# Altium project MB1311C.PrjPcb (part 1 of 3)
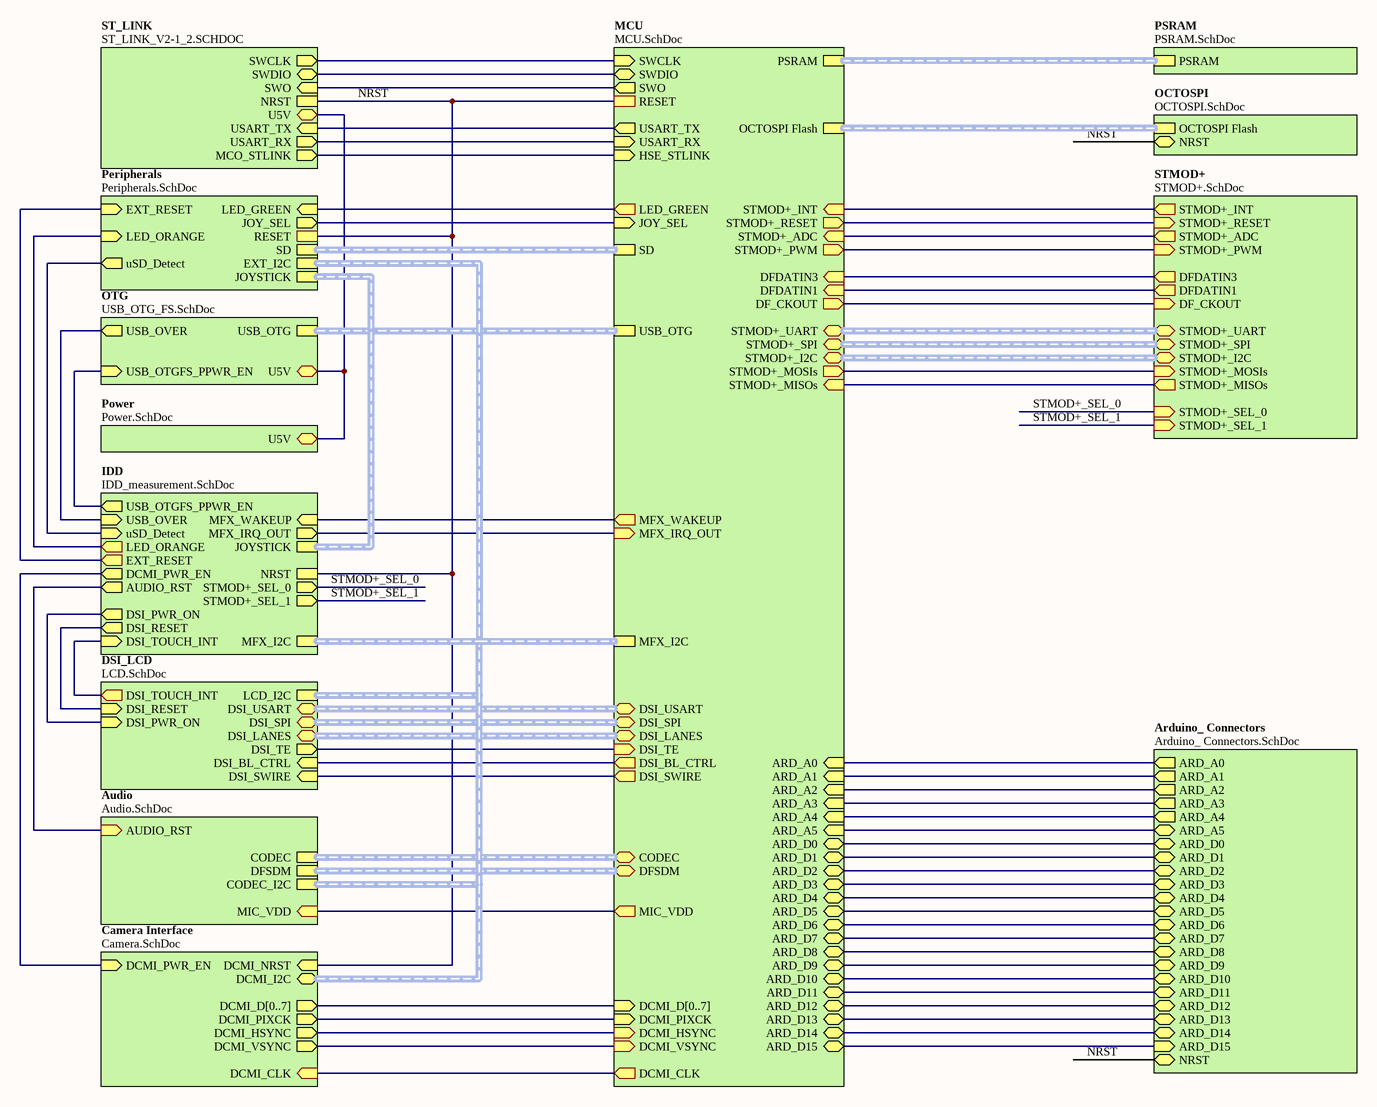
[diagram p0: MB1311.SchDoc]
14 sheets, 364 parts. Net scope: hierarchical (ports join the sheet entries above them; power ports are global).
Board file: MB1311C.PcbDoc
Sheets:
  MB1311.SchDoc
    Arduino_ Connectors = Arduino_ Connectors.SchDoc
    Camera Interface = Camera.SchDoc
    IDD = IDD_measurement.SchDoc
    DSI_LCD = LCD.SchDoc
    MCU = MCU.SchDoc
    Peripherals = Peripherals.SchDoc
    Power = Power.SchDoc
    PSRAM = PSRAM.SchDoc
    OCTOSPI = OCTOSPI.SchDoc
    ST_LINK = ST_LINK_V2-1_2.SCHDOC
    OTG = USB_OTG_FS.SchDoc
    STMOD+ = STMOD+.SchDoc
    Audio = Audio.SchDoc

## Sheet MB1311.SchDoc: MB1311-TOP
size A3; Date: 18/07/2017; Author: P.A.; CompanyName: STMicroelectronics; Organization: Microcontrollers Division; Address1: 12, Rue Jules HOROWITZ; Address2: 38019 Grenoble; Address3: FRANCE; DocumentNumber: MB1311; Revision: C; SheetNumber: 1; SheetTotal: 14; Project: STM32L4R9I-DISCO; PageSetup: Record=PageOptions¦CenterHorizontal=True¦CenterVertical=True¦PrintScale=1.00¦XCorrection=1.00¦YCorrection=1.00¦PrintKind=1¦BorderSize=5000000¦LeftOffset=0¦BottomOffset=0¦Orientation=2¦PaperLength=1000¦PaperWidth=1000¦Scale=100¦PaperSource=7¦PrintQuality=-3¦MediaType=1¦DitherType=10¦PrintScaleMode=1¦PaperKind=Letter¦PaperIndex=1

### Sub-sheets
Arduino_ Connectors = Arduino_ Connectors.SchDoc: NRST (bidir), ARD_A0 (out), ARD_A1 (out), ARD_A2 (out), ARD_A3 (out), ARD_A4 (out), ARD_A5 (bidir), ARD_D5 (bidir), ARD_D4 (bidir), ARD_D3 (bidir), ARD_D2 (bidir), ARD_D1 (bidir), ARD_D0 (bidir), ARD_D13 (bidir), ARD_D12 (bidir), ARD_D11 (bidir), ARD_D10 (bidir), ARD_D9 (bidir), ARD_D8 (bidir), ARD_D6 (bidir), ARD_D7 (bidir), ARD_D15 (in), ARD_D14 (bidir)
Audio = Audio.SchDoc: CODEC (harness SAI), CODEC_I2C (harness I2C), DFSDM (harness DFSDM), MIC_VDD (in), AUDIO_RST (in)
Camera Interface = Camera.SchDoc: DCMI_D[0..7] (out), DCMI_NRST (in), DCMI_PWR_EN (in), DCMI_VSYNC (out), DCMI_HSYNC (out), DCMI_PIXCK (out), DCMI_I2C (harness I2C), DCMI_CLK (in)
DSI_LCD = LCD.SchDoc: LCD_I2C (harness I2C), DSI_RESET (in), DSI_TOUCH_INT (out), DSI_USART (harness DSI_USART), DSI_SPI (harness DSI_SPI), DSI_BL_CTRL (in), DSI_PWR_ON (in), DSI_SWIRE (in), DSI_TE (out), DSI_LANES (harness DSI_LANES)
IDD = IDD_measurement.SchDoc: MFX_IRQ_OUT (out), MFX_WAKEUP (in), NRST, MFX_I2C (harness I2C), USB_OTGFS_PPWR_EN (out), DCMI_PWR_EN (out), uSD_Detect (in), USB_OVER (in), DSI_RESET (out), LED_ORANGE (out), DSI_TOUCH_INT (in), AUDIO_RST (out), EXT_RESET (out), DSI_PWR_ON (out), JOYSTICK (harness JOYSTICK), STMOD+_SEL_0 (out), STMOD+_SEL_1 (out)
MCU = MCU.SchDoc: OCTOSPI Flash (harness OCTOSPI), PSRAM (harness PSRAM), SD (harness SD), USB_OTG (harness USB_OTG), MFX_IRQ_OUT (in), MFX_WAKEUP (out), ARD_A0 (in), MFX_I2C (harness I2C), ARD_A1 (in), ARD_A2 (in), ARD_A3 (in), ARD_A4 (in), ARD_A5 (in), ARD_D0 (bidir), ARD_D1 (bidir), ARD_D2 (bidir), ARD_D3 (bidir), ARD_D4 (bidir), ARD_D5 (bidir), ARD_D6 (bidir), ARD_D7 (bidir), ARD_D8 (bidir), ARD_D9 (bidir), ARD_D10 (bidir), ARD_D11 (bidir), ARD_D12 (bidir), ARD_D13 (bidir), ARD_D14 (bidir), ARD_D15 (bidir), USART_TX (out), USART_RX (in), SWCLK (in), SWDIO (bidir), SWO (out), DCMI_D[0..7] (in), DCMI_VSYNC (in), DCMI_HSYNC (in), DCMI_PIXCK (in), STMOD+_UART (harness UART), STMOD+_I2C (harness I2C), STMOD+_INT (in), STMOD+_RESET (out), STMOD+_ADC (in), STMOD+_PWM (out), STMOD+_MOSIs (out), STMOD+_MISOs (in), STMOD+_SPI (harness SPI), DFDATIN3 (in), DFDATIN1 (in), DFSDM (harness DFSDM), MIC_VDD (out), CODEC (harness SAI), LED_GREEN (out), RESET, DCMI_CLK (out), DF_CKOUT (out), DSI_USART (harness DSI_USART), DSI_SPI (harness DSI_SPI), JOY_SEL (in), DSI_TE (in), DSI_LANES (harness DSI_LANES), DSI_BL_CTRL (out), DSI_SWIRE (out), HSE_STLINK (in)
OCTOSPI = OCTOSPI.SchDoc: OCTOSPI Flash (harness OCTOSPI), NRST (bidir)
OTG = USB_OTG_FS.SchDoc: USB_OTG (harness USB_OTG), USB_OTGFS_PPWR_EN (in), USB_OVER (out), U5V
Peripherals = Peripherals.SchDoc: LED_GREEN (in), SD (harness SD), JOYSTICK (harness JOYSTICK), LED_ORANGE (in), uSD_Detect (out), RESET, JOY_SEL (out), EXT_RESET (in), EXT_I2C (harness I2C)
Power = Power.SchDoc: U5V
PSRAM = PSRAM.SchDoc: PSRAM (harness PSRAM)
ST_LINK = ST_LINK_V2-1_2.SCHDOC: NRST, SWCLK (out), SWDIO (bidir), SWO (in), USART_TX (in), USART_RX (out), U5V, MCO_STLINK (out)
STMOD+ = STMOD+.SchDoc: STMOD+_INT (out), STMOD+_RESET (in), STMOD+_ADC (out), DFDATIN3 (out), STMOD+_PWM (in), DFDATIN1 (out), STMOD+_UART (harness UART), STMOD+_SPI (harness SPI), STMOD+_I2C (harness I2C), STMOD+_MOSIs (in), STMOD+_MISOs (out), DF_CKOUT (in), STMOD+_SEL_1 (in), STMOD+_SEL_0 (in)

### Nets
ARD_A0: sheet Arduino_ Connectors/ARD_A0, sheet MCU/ARD_A0
ARD_A1: sheet Arduino_ Connectors/ARD_A1, sheet MCU/ARD_A1
ARD_A2: sheet Arduino_ Connectors/ARD_A2, sheet MCU/ARD_A2
ARD_A3: sheet Arduino_ Connectors/ARD_A3, sheet MCU/ARD_A3
ARD_A4: sheet Arduino_ Connectors/ARD_A4, sheet MCU/ARD_A4
ARD_A5: sheet Arduino_ Connectors/ARD_A5, sheet MCU/ARD_A5, sheet MCU/STMOD+_PWM, sheet STMOD+/STMOD+_PWM
ARD_D0: sheet Arduino_ Connectors/ARD_D0, sheet MCU/ARD_D0
ARD_D1: sheet Arduino_ Connectors/ARD_D1, sheet MCU/ARD_D1
ARD_D2: sheet Arduino_ Connectors/ARD_D2, sheet MCU/ARD_D2
ARD_D3: sheet Arduino_ Connectors/ARD_D3, sheet MCU/ARD_D3
ARD_D4: sheet Arduino_ Connectors/ARD_D4, sheet MCU/ARD_D4
ARD_D5: sheet Arduino_ Connectors/ARD_D5, sheet MCU/ARD_D5
ARD_D6: sheet Arduino_ Connectors/ARD_D6, sheet MCU/ARD_D6
ARD_D7: sheet Arduino_ Connectors/ARD_D7, sheet Camera Interface/DCMI_HSYNC, sheet MCU/ARD_D7, sheet MCU/DCMI_HSYNC, sheet MCU/STMOD+_ADC, sheet STMOD+/STMOD+_ADC
ARD_D8: sheet Arduino_ Connectors/ARD_D8, sheet MCU/ARD_D8
ARD_D9: sheet Arduino_ Connectors/ARD_D9, sheet MCU/ARD_D9
ARD_D10: sheet Arduino_ Connectors/ARD_D10, sheet MCU/ARD_D10
ARD_D11: sheet Arduino_ Connectors/ARD_D11, sheet MCU/ARD_D11
ARD_D12: sheet Arduino_ Connectors/ARD_D12, sheet MCU/ARD_D12
ARD_D13: sheet Arduino_ Connectors/ARD_D13, sheet MCU/ARD_D13
ARD_D14: sheet Arduino_ Connectors/ARD_D14, sheet MCU/ARD_D14
ARD_D15: sheet Arduino_ Connectors/ARD_D15, sheet MCU/ARD_D15
CKOUT: sheet MCU/DF_CKOUT, sheet STMOD+/DF_CKOUT
DATIN1: sheet MCU/DFDATIN1, sheet STMOD+/DFDATIN1
DCMI_CLK: sheet Camera Interface/DCMI_CLK, sheet DSI_LCD/DSI_SWIRE, sheet MCU/DCMI_CLK, sheet MCU/DSI_SWIRE
DCMI_D0: sheet MCU/STMOD+_INT, sheet STMOD+/STMOD+_INT
DCMI_D1: sheet MCU/DFDATIN3, sheet STMOD+/DFDATIN3
DCMI_D7: sheet MCU/STMOD+_RESET, sheet STMOD+/STMOD+_RESET
DCMI_PIXCLK: sheet Camera Interface/DCMI_PIXCK, sheet MCU/DCMI_PIXCK
DCMI_PWR_EN: sheet Camera Interface/DCMI_PWR_EN, sheet IDD/DCMI_PWR_EN
DCMI_VSYNC: sheet Camera Interface/DCMI_VSYNC, sheet MCU/DCMI_VSYNC
DSI_BL_CTRL: sheet DSI_LCD/DSI_BL_CTRL, sheet MCU/DSI_BL_CTRL
DSI_PWR_ON: sheet IDD/DSI_PWR_ON, sheet DSI_LCD/DSI_PWR_ON
DSI_TE: sheet DSI_LCD/DSI_TE, sheet MCU/DSI_TE
JOY_SEL: sheet MCU/JOY_SEL, sheet Peripherals/JOY_SEL
LED_GREEN: sheet MCU/LED_GREEN, sheet Peripherals/LED_GREEN
MCO: sheet MCU/HSE_STLINK, sheet ST_LINK/MCO_STLINK
MFX_IRQ_OUT: sheet IDD/MFX_IRQ_OUT, sheet MCU/MFX_IRQ_OUT
MFX_WAKEUP: sheet IDD/MFX_WAKEUP, sheet MCU/MFX_WAKEUP
MIC_VDD: sheet MCU/MIC_VDD, sheet Audio/MIC_VDD
NRST: sheet Arduino_ Connectors/NRST, sheet Camera Interface/DCMI_NRST, sheet IDD/NRST, sheet MCU/RESET, sheet Peripherals/RESET, sheet OCTOSPI/NRST, sheet ST_LINK/NRST  [project net DCMI_NRST]
SPI2_MISOs: sheet MCU/STMOD+_MISOs, sheet STMOD+/STMOD+_MISOs
SPI2_MOSIs: sheet MCU/STMOD+_MOSIs, sheet STMOD+/STMOD+_MOSIs
STMOD+_SEL_0: sheet IDD/STMOD+_SEL_0, sheet STMOD+/STMOD+_SEL_0  [project net PMOD_SEL_0]
STMOD+_SEL_1: sheet IDD/STMOD+_SEL_1, sheet STMOD+/STMOD+_SEL_1  [project net PMOD_SEL_1]
SWCLK: sheet MCU/SWCLK, sheet ST_LINK/SWCLK
SWDIO: sheet MCU/SWDIO, sheet ST_LINK/SWDIO
SWO: sheet MCU/SWO, sheet ST_LINK/SWO
TOUCH_INT: sheet IDD/DSI_TOUCH_INT, sheet DSI_LCD/DSI_TOUCH_INT
USART2_RX: sheet MCU/USART_RX, sheet ST_LINK/USART_RX
USART2_TX: sheet MCU/USART_TX, sheet ST_LINK/USART_TX
USB_OTGFS_OVRCR: sheet IDD/USB_OVER, sheet OTG/USB_OVER
USB_OTGFS_VBUS: sheet Power/U5V, sheet ST_LINK/U5V, sheet OTG/U5V
uSD_Detect: sheet IDD/uSD_Detect, sheet Peripherals/uSD_Detect
NetCN4_57: sheet IDD/DSI_RESET, sheet DSI_LCD/DSI_RESET
NetR3_1: sheet IDD/LED_ORANGE, sheet Peripherals/LED_ORANGE
NetR41_2: sheet IDD/USB_OTGFS_PPWR_EN, sheet OTG/USB_OTGFS_PPWR_EN
NetR83_2: sheet IDD/AUDIO_RST, sheet Audio/AUDIO_RST
NetR112_2: sheet IDD/EXT_RESET, sheet Peripherals/EXT_RESET

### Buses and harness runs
bus sheet Camera Interface/DCMI_D[0..7] = sheet MCU/DCMI_D[0..7]
harness sheet Audio/CODEC = sheet MCU/CODEC
harness sheet Audio/CODEC_I2C = sheet Camera Interface/DCMI_I2C = sheet DSI_LCD/LCD_I2C = sheet IDD/MFX_I2C = sheet MCU/MFX_I2C = sheet Peripherals/EXT_I2C
harness sheet Audio/DFSDM = sheet MCU/DFSDM
harness sheet DSI_LCD/DSI_LANES = sheet MCU/DSI_LANES
harness sheet DSI_LCD/DSI_SPI = sheet MCU/DSI_SPI
harness sheet DSI_LCD/DSI_USART = sheet MCU/DSI_USART
harness sheet IDD/JOYSTICK = sheet Peripherals/JOYSTICK
harness sheet MCU/OCTOSPI Flash = sheet OCTOSPI/OCTOSPI Flash
harness sheet MCU/PSRAM = sheet PSRAM/PSRAM
harness sheet MCU/SD = sheet Peripherals/SD
harness sheet MCU/STMOD+_I2C = sheet STMOD+/STMOD+_I2C
harness sheet MCU/STMOD+_SPI = sheet STMOD+/STMOD+_SPI
harness sheet MCU/STMOD+_UART = sheet STMOD+/STMOD+_UART
harness sheet MCU/USB_OTG = sheet OTG/USB_OTG

## Sheet Arduino_ Connectors.SchDoc: Arduino Uno connector
size A4; Author: P.A.; CompanyName: STMicroelectronics; Organization: Microcontrollers Division; Address1: 12, Rue Jules HOROWITZ; Address2: 38019 Grenoble; Address3: FRANCE; DocumentNumber: MB1311; Revision: C; SheetNumber: 3; SheetTotal: 14; Project: STM32L4R9I-DISCO
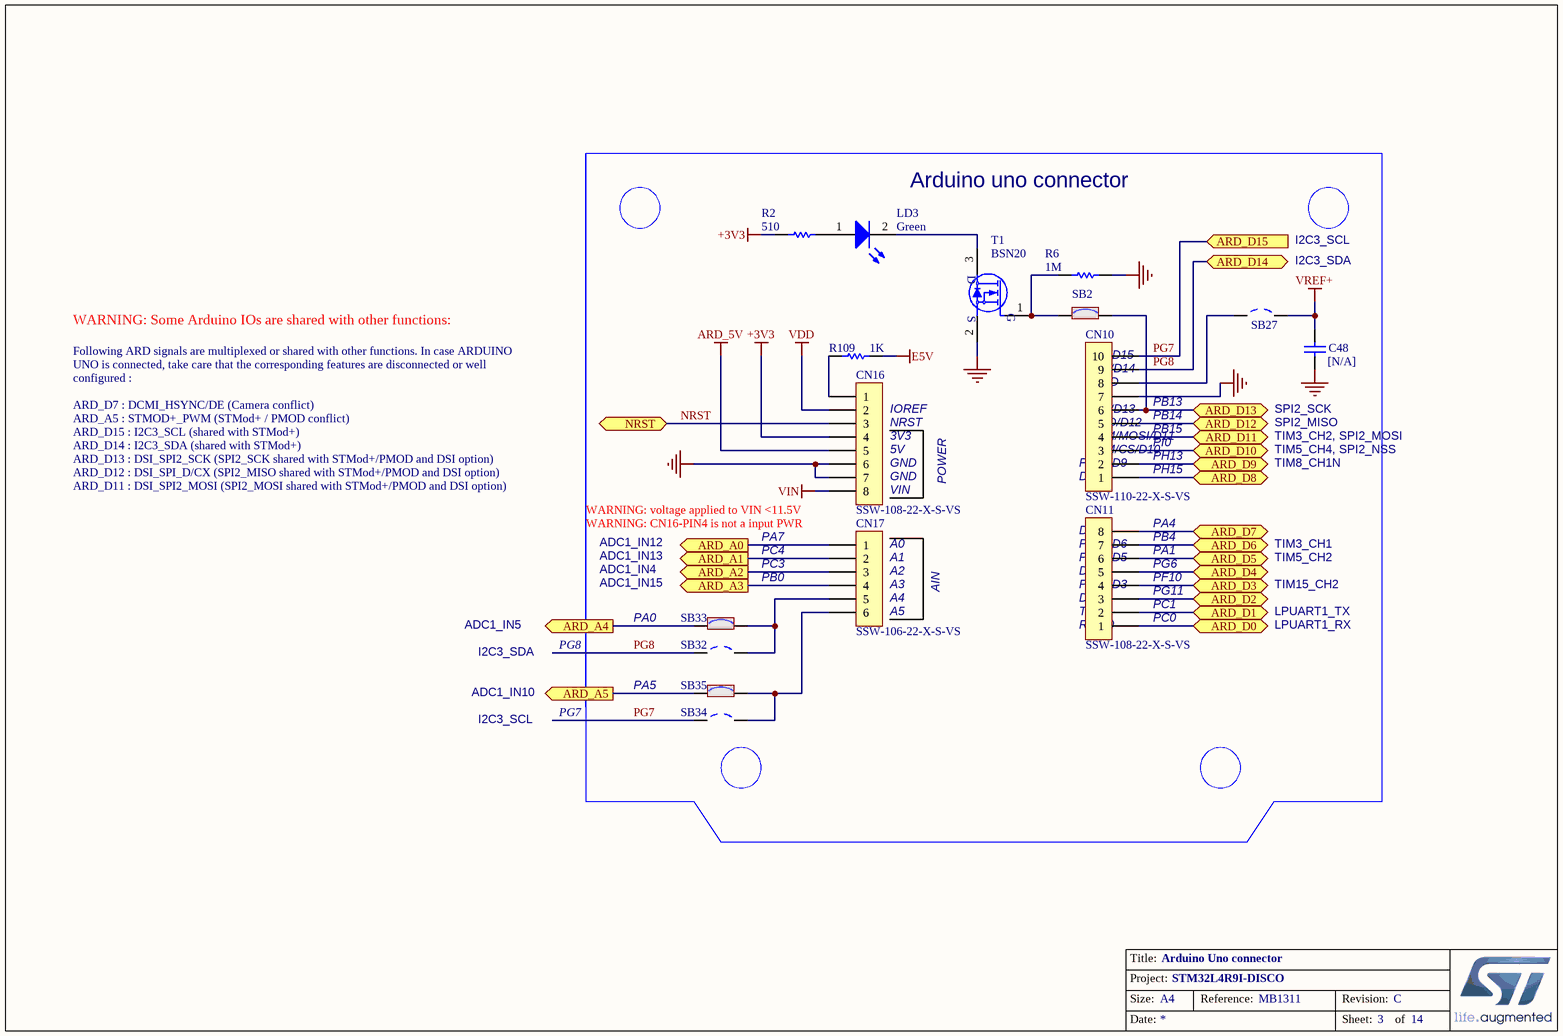
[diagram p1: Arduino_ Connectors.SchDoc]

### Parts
C48  [N/A]  [C0603]
CN10  SSW-110-22-X-S-VS  [CON_SAMTEC_SSW-110-22-X-S-VS]
CN11  SSW-108-22-X-S-VS  [CON_SAMTEC_SSW-108-22-X-S-VS]
CN16  SSW-108-22-X-S-VS  [CON_SAMTEC_SSW-108-22-X-S-VS]
CN17  SSW-106-22-X-S-VS  [CON_SAMTEC_SSW-106-22-X-S-VS]
LD3  Corlor: Green  [LED_0603_GREEN_H0P8]  (hidden comment: 19-213SY6C/S530-E2/TR8LED)
R2  value 510  [R0603]  (hidden comment: RC0603JR-07510RL)
R6  1M  [R0603]
R109  1K  [R0603]
SB2  Solder Bridge ON  [SOLDER-BRIDGE_R0603-0R]  (value not drawn)
SB27  Solder Bridge OFF  [SOLDER-BRIDGE_R0603-0R]  (value not drawn)
SB32  Solder Bridge OFF  [SOLDER-BRIDGE_R0603-0R]  (value not drawn)
SB33  Solder Bridge ON  [SOLDER-BRIDGE_R0603-0R]  (value not drawn)
SB34  Solder Bridge OFF  [SOLDER-BRIDGE_R0603-0R]  (value not drawn)
SB35  Solder Bridge ON  [SOLDER-BRIDGE_R0603-0R]  (value not drawn)
T1  BSN20  [MOS_SOT23]

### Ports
ARD_A0 (out), ARD_A1 (out), ARD_A2 (out), ARD_A3 (out), ARD_A4 (out), ARD_A5 (out), ARD_D0 (bidir), ARD_D1 (bidir), ARD_D2 (bidir), ARD_D3 (bidir), ARD_D4 (bidir), ARD_D5 (bidir), ARD_D6 (bidir), ARD_D7 (bidir), ARD_D8 (bidir), ARD_D9 (bidir), ARD_D10 (bidir), ARD_D11 (bidir), ARD_D12 (bidir), ARD_D13 (bidir), ARD_D14 (bidir), ARD_D15 (in), NRST (bidir)

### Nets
+3V3: CN16.4 R2.1
ARD_5V: CN16.5
E5V: R109.1
GND: C48.2 CN10.7 CN16.6 CN16.7 R6.2 T1.2(S)
VDD: CN16.2
VIN: CN16.8
VREF+: C48.1 SB27.2
ARD_A0: CN17.1 ; port ARD_A0
ARD_A1: CN17.2 ; port ARD_A1
ARD_A2: CN17.3 ; port ARD_A2
ARD_A3: CN17.4 ; port ARD_A3
ARD_A4: SB33.1 ; port ARD_A4
ARD_A5: SB35.1 ; port ARD_A5
ARD_D0: CN11.1 ; port ARD_D0
ARD_D1: CN11.2 ; port ARD_D1
ARD_D2: CN11.3 ; port ARD_D2
ARD_D3: CN11.4 ; port ARD_D3
ARD_D4: CN11.5 ; port ARD_D4
ARD_D5: CN11.6 ; port ARD_D5
ARD_D6: CN11.7 ; port ARD_D6
ARD_D7: CN11.8 ; port ARD_D7
ARD_D8: CN10.1 ; port ARD_D8
ARD_D9: CN10.2 ; port ARD_D9
ARD_D10: CN10.3 ; port ARD_D10
ARD_D11: CN10.4 ; port ARD_D11
ARD_D12: CN10.5 ; port ARD_D12
ARD_D13: CN10.6 SB2.2 ; port ARD_D13
NRST: CN16.3 ; port NRST  [project net DCMI_NRST]
PG7: CN10.10 SB34.1 ; port ARD_D15  [project net ARD_D15]
PG8: CN10.9 SB32.1 ; port ARD_D14  [project net ARD_D14]
NetCN10_8: CN10.8 SB27.1
NetCN16_1: CN16.1 R109.2
NetCN17_5: CN17.5 SB32.2 SB33.2
NetCN17_6: CN17.6 SB34.2 SB35.2
NetLD3_1: LD3.1(A) R2.2
NetLD3_2: LD3.2(K) T1.3(D)
NetR6_1: R6.1 SB2.1 T1.1(G)

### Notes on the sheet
- Arduino uno connector
- I2C3_SCL
- I2C3_SDA
- WARNING: Some Arduino IOs are shared with other functions:
- (near CN10) SDA/D14
- SCL/D15
- (near CN10) AVDD
- IOREF
- (near CN16) NRST
- (near CN16) 3V3
- (near CN10) SCK/D13
- (near CN10) MISO/D12
- (near CN10) PWM/MOSI/D11
- (near CN10) GND
- (near CN10) PI0
- (near CN10) PB15
- (near CN10) PB14
- (near CN10) PB13
- TIM3_CH2, SPI2_MOSI
- SPI2_MISO
- (near C48) SPI2_SCK
- Following ARD signals are multiplexed or shared with other functions. In case ARDUINO UNO is connected, take care that the corresponding features are disconnected or well configured :
  ARD_D7 : DCMI_HSYNC/DE (Camera conflict)
  ARD_A5 : STMOD+_PWM (STMod+ / PMOD conflict)
  ARD_D15 : I2C3_SCL (shared with STMod+)
  ARD_D14 : I2C3_SDA (shared with STMod+)
  ARD_D13 : DSI_SPI2_SCK (SPI2_SCK shared with STMod+/PMOD and DSI option)
  ARD_D12 : DSI_SPI_D/CX (SPI2_MISO shared with STMod+/PMOD and DSI option)
  ARD_D11 : DSI_SPI2_MOSI (SPI2_MOSI shared with STMod+/PMOD and DSI option)
- WARNING: voltage applied to VIN <11.5V
- (near CN16) 5V
- (near CN16) GND
- (near CN16) VIN
- POWER
- (near CN10) D8
- (near CN10) PWM/D9
- (near CN10) PWM/CS/D10
- (near CN10) PH15
- (near CN10) PH13
- TIM8_CH1N
- TIM5_CH4, SPI2_NSS
- WARNING: CN16-PIN4 is not a input PWR
- ADC1_IN4
- ADC1_IN13
- ADC1_IN12
- ADC1_IN15
- PA7
- PC4
- PC3
- PB0
- (near CN17) A0
- (near CN17) A1
- (near CN17) A2
- (near CN11) D4
- (near CN11) PWM/D5
- (near CN11) PWM/D6
- (near CN11) D7
- (near CN11) PG6
- (near CN11) PA1
- (near CN11) PB4
- PA4
- (near CN11) PF10
- TIM5_CH2
- TIM3_CH1
- ADC1_IN5
- PG8
- PA0
- (near CN17) A3
- (near CN17) A4
- (near CN17) A5
- AIN
- (near CN11) RX/D0
- (near CN11) TX/D1
- (near CN11) D2
- (near CN11) PWM/D3
- (near CN11) PC1
- (near CN11) PC0
- (near CN11) PG11
- LPUART1_TX
- LPUART1_RX
- TIM15_CH2
- ADC1_IN10
- PG7
- PA5

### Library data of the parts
C48 = Cap: Capacitor,100nF,10%,16V,X7R,0603,YAGEO; Manuf_Part_1: CC0603KRX7R7BB104; Ordered by: Subcon
CN10 = Header 10X1_Female: Header, 10-Pin, Single row,female; Manuf_1: SAMTEC; Ordered by: Subcon; ECCN_US/EU: NA
CN11 CN16 = Header 8X1_Female: Header, 8-Pin, Single row,female; Manuf_1: SAMTEC; Ordered by: Subcon; ECCN_US/EU: NA
CN17 = Header 6X1_Female: Header, 6-Pin, Single row,female; Manuf_1: SAMTEC; Ordered by: Subcon; ECCN_US/EU: NA
LD3 = LED2: LED,Green,0603; Manuf_1: Everlight; Ordered by: Subcon; ECCN_US/EU: EAR99/NEC
R2 = res1: Resistor, 510R , 0603,1%,YAGEO; Ordered by: Subcon; ECCN_US/EU: NA
R6 = res1: Resistor, 1M , 0603; Ordered by: Subcon; ECCN_US/EU: NA
R109 = res1: Resistor,1K,0603,1%; Manuf_1: YAGEO; Manuf_Part_1: RC0603FR-071KL; Ordered by: Subcon; ECCN_US/EU: NA
SB2 SB33 SB35 = SB_ON: Manuf_1: YAGEO; Manuf_Part_1: RC0603JR-070RL; Solder: YES; Ordered By: Subcon
SB27 SB32 SB34 = SB_OFF: Solder: NO
T1 = 2N7000: Manuf_1: DIODES; Manuf_Part_1: BSN20-7; Ordered by: Subcon

## Sheet Camera.SchDoc: Camera
size A4; Author: P.A.; CompanyName: STMicroelectronics; Organization: Microcontrollers Division; Address1: 12, Rue Jules HOROWITZ; Address2: 38019 Grenoble; Address3: FRANCE; DocumentNumber: MB1311; Revision: C; SheetNumber: 12; SheetTotal: 14; Project: STM32L4R9I-DISCO
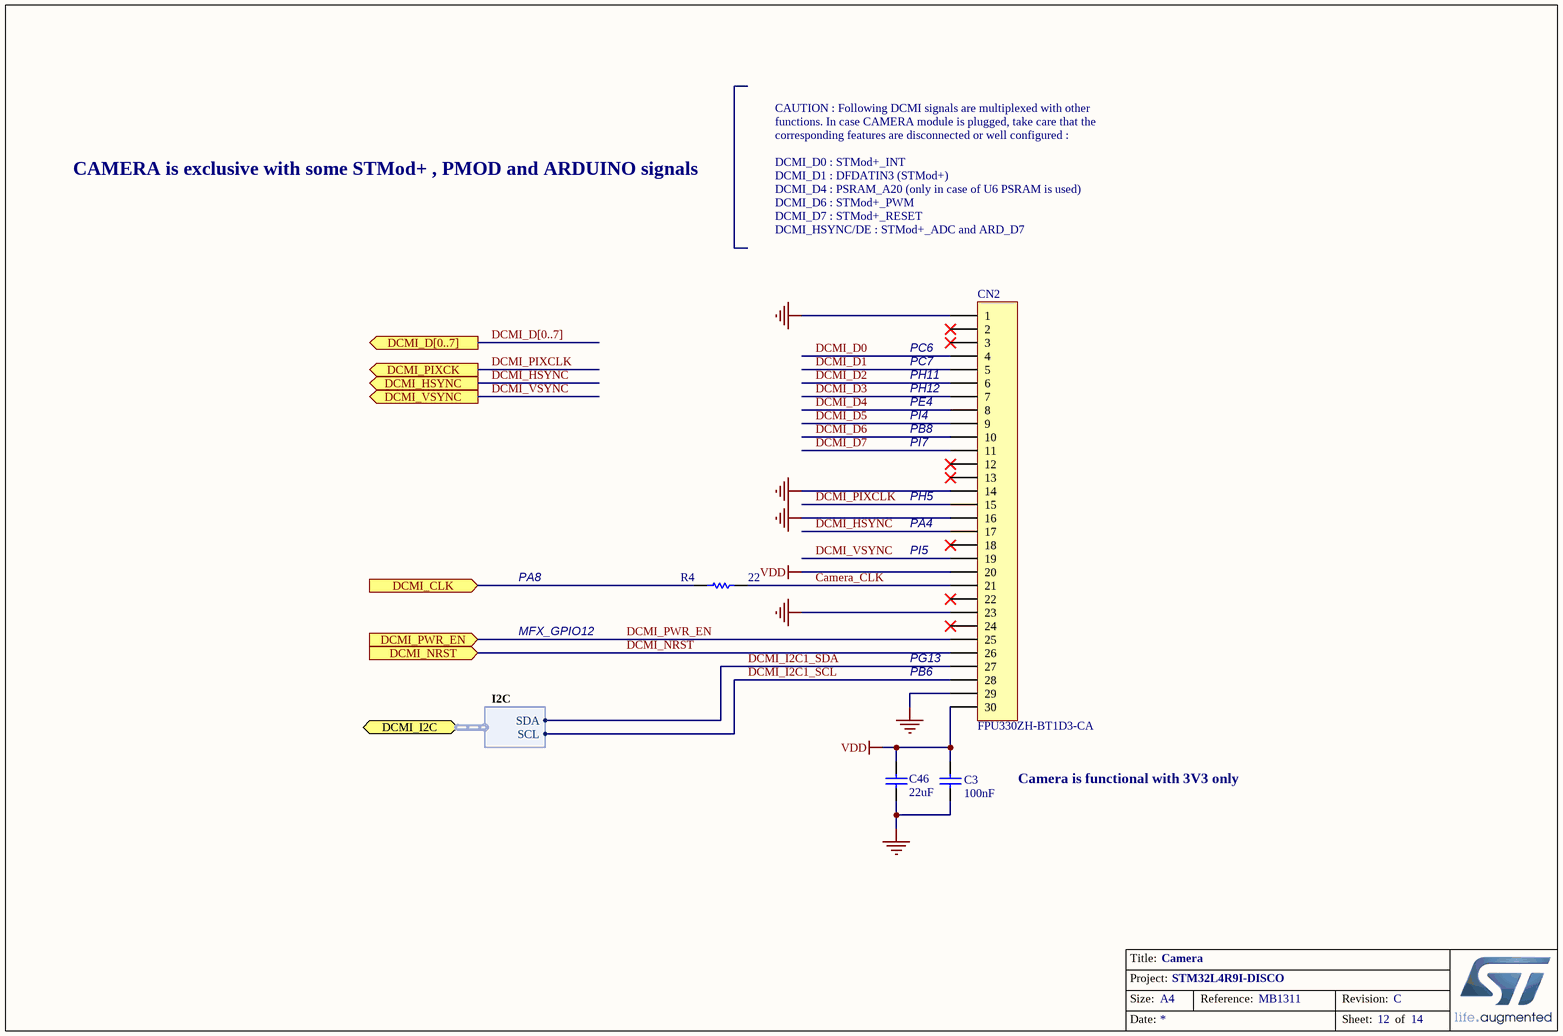
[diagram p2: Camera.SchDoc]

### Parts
C3  value 100nF  [C0603]  (hidden comment: CC0603KRX7R7BB104)
C46  value 22uF  [CPOL_TAJ-A_1206_H180]  (hidden comment: GRM31CR61C226KE15L)
CN2  FPU330ZH-BT1D3-CA  [CON_TOWNES_FPU330ZH-BT1D3-CA_P050]
R4  value 22  [R0603]  (hidden comment: RC0603JR-0722RL)

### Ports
DCMI_CLK (in), DCMI_D[0..7] (out), DCMI_HSYNC (out), DCMI_I2C (harness I2C), DCMI_NRST (in), DCMI_PIXCK (out), DCMI_PWR_EN (in), DCMI_VSYNC (out)

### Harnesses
I2C: SDA, SCL

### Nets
GND: C3.2 C46.1 CN2.1 CN2.14 CN2.16 CN2.23 CN2.29
VDD: C3.1 C46.2 CN2.20 CN2.30
Camera_CLK: CN2.21 R4.1
DCMI_CLK: R4.2 ; port DCMI_CLK
DCMI_D0: CN2.4
DCMI_D1: CN2.5
DCMI_D2: CN2.6
DCMI_D3: CN2.7
DCMI_D4: CN2.8
DCMI_D5: CN2.9
DCMI_D6: CN2.10
DCMI_D7: CN2.11
DCMI_HSYNC: CN2.17 ; port DCMI_HSYNC  [project net ARD_D7]
DCMI_I2C1_SCL: CN2.28 ; port DCMI_I2C.SCL
DCMI_I2C1_SDA: CN2.27 ; port DCMI_I2C.SDA
DCMI_NRST: CN2.26 ; port DCMI_NRST
DCMI_PIXCLK: CN2.15 ; port DCMI_PIXCK
DCMI_PWR_EN: CN2.25 ; port DCMI_PWR_EN
DCMI_VSYNC: CN2.19 ; port DCMI_VSYNC

Not connected (* = marked no-connect by the designer): CN2 2* 3* 12* 13* 18* 22* 24*

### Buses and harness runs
bus DCMI_D[0..7] = port DCMI_D[0..7]

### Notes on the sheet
- CAMERA is exclusive with some STMod+ , PMOD and ARDUINO signals
- (near CN2) CAUTION : Following DCMI signals are multiplexed with other functions. In case CAMERA module is plugged, take care that the corresponding features are disconnected or well configured :
  DCMI_D0 : STMod+_INT
  DCMI_D1 : DFDATIN3 (STMod+)
  DCMI_D4 : PSRAM_A20 (only in case of U6 PSRAM is used)
  DCMI_D6 : STMod+_PWM
  DCMI_D7 : STMod+_RESET
  DCMI_HSYNC/DE : STMod+_ADC and ARD_D7
- (near CN2) PC7
- (near CN2) PH11
- (near CN2) PC6
- (near CN2) PB8
- (near CN2) PH12
- (near CN2) PE4
- (near CN2) PI4
- (near CN2) PI7
- (near CN2) PH5
- PA8
- (near CN2) PA4
- (near CN2) PI5
- MFX_GPIO12
- (near CN2) PB6
- (near CN2) PG13
- Camera is functional with 3V3 only

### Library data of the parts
C3 = Cap: Capacitor,100nF,10%,16V,X7R,0603,YAGEO; Ordered by: Subcon
C46 = Cap_22µF_X5R_16V_10%_1206: Ceramic Capacitor,22uF,10%,16V,X5R,GRM31CR61C226KE15L; Manuf_1: Murata; Ordered by: Subcon; ECCN_US/EU: NA
CN2 = FPU330ZH-BT1D3-CA: TOWNES -  Connector FFC/FPC ZIF 0.5mm 30 pins, Lower Contacts; Manuf_Part_2: TFP-A330ZH-BT1-ECX; Ordered by: Subcon
R4 = res1: Resistor, 22 ,0603,1%,YAGEO; Ordered by: Subcon; ECCN_US/EU: NA

## Sheet IDD_measurement.SchDoc: IDD measurement / MFX (Multi Function eXpander)
size A3; Date: 18/07/2017; Author: P.A.; CompanyName: STMicroelectronics; Organization: Microcontrollers Division; Address1: 12, Rue Jules HOROWITZ; Address2: 38019 Grenoble; Address3: FRANCE; DocumentNumber: MB1311; Revision: C; SheetNumber: 9; SheetTotal: 14; Project: STM32L4R9I-DISCO
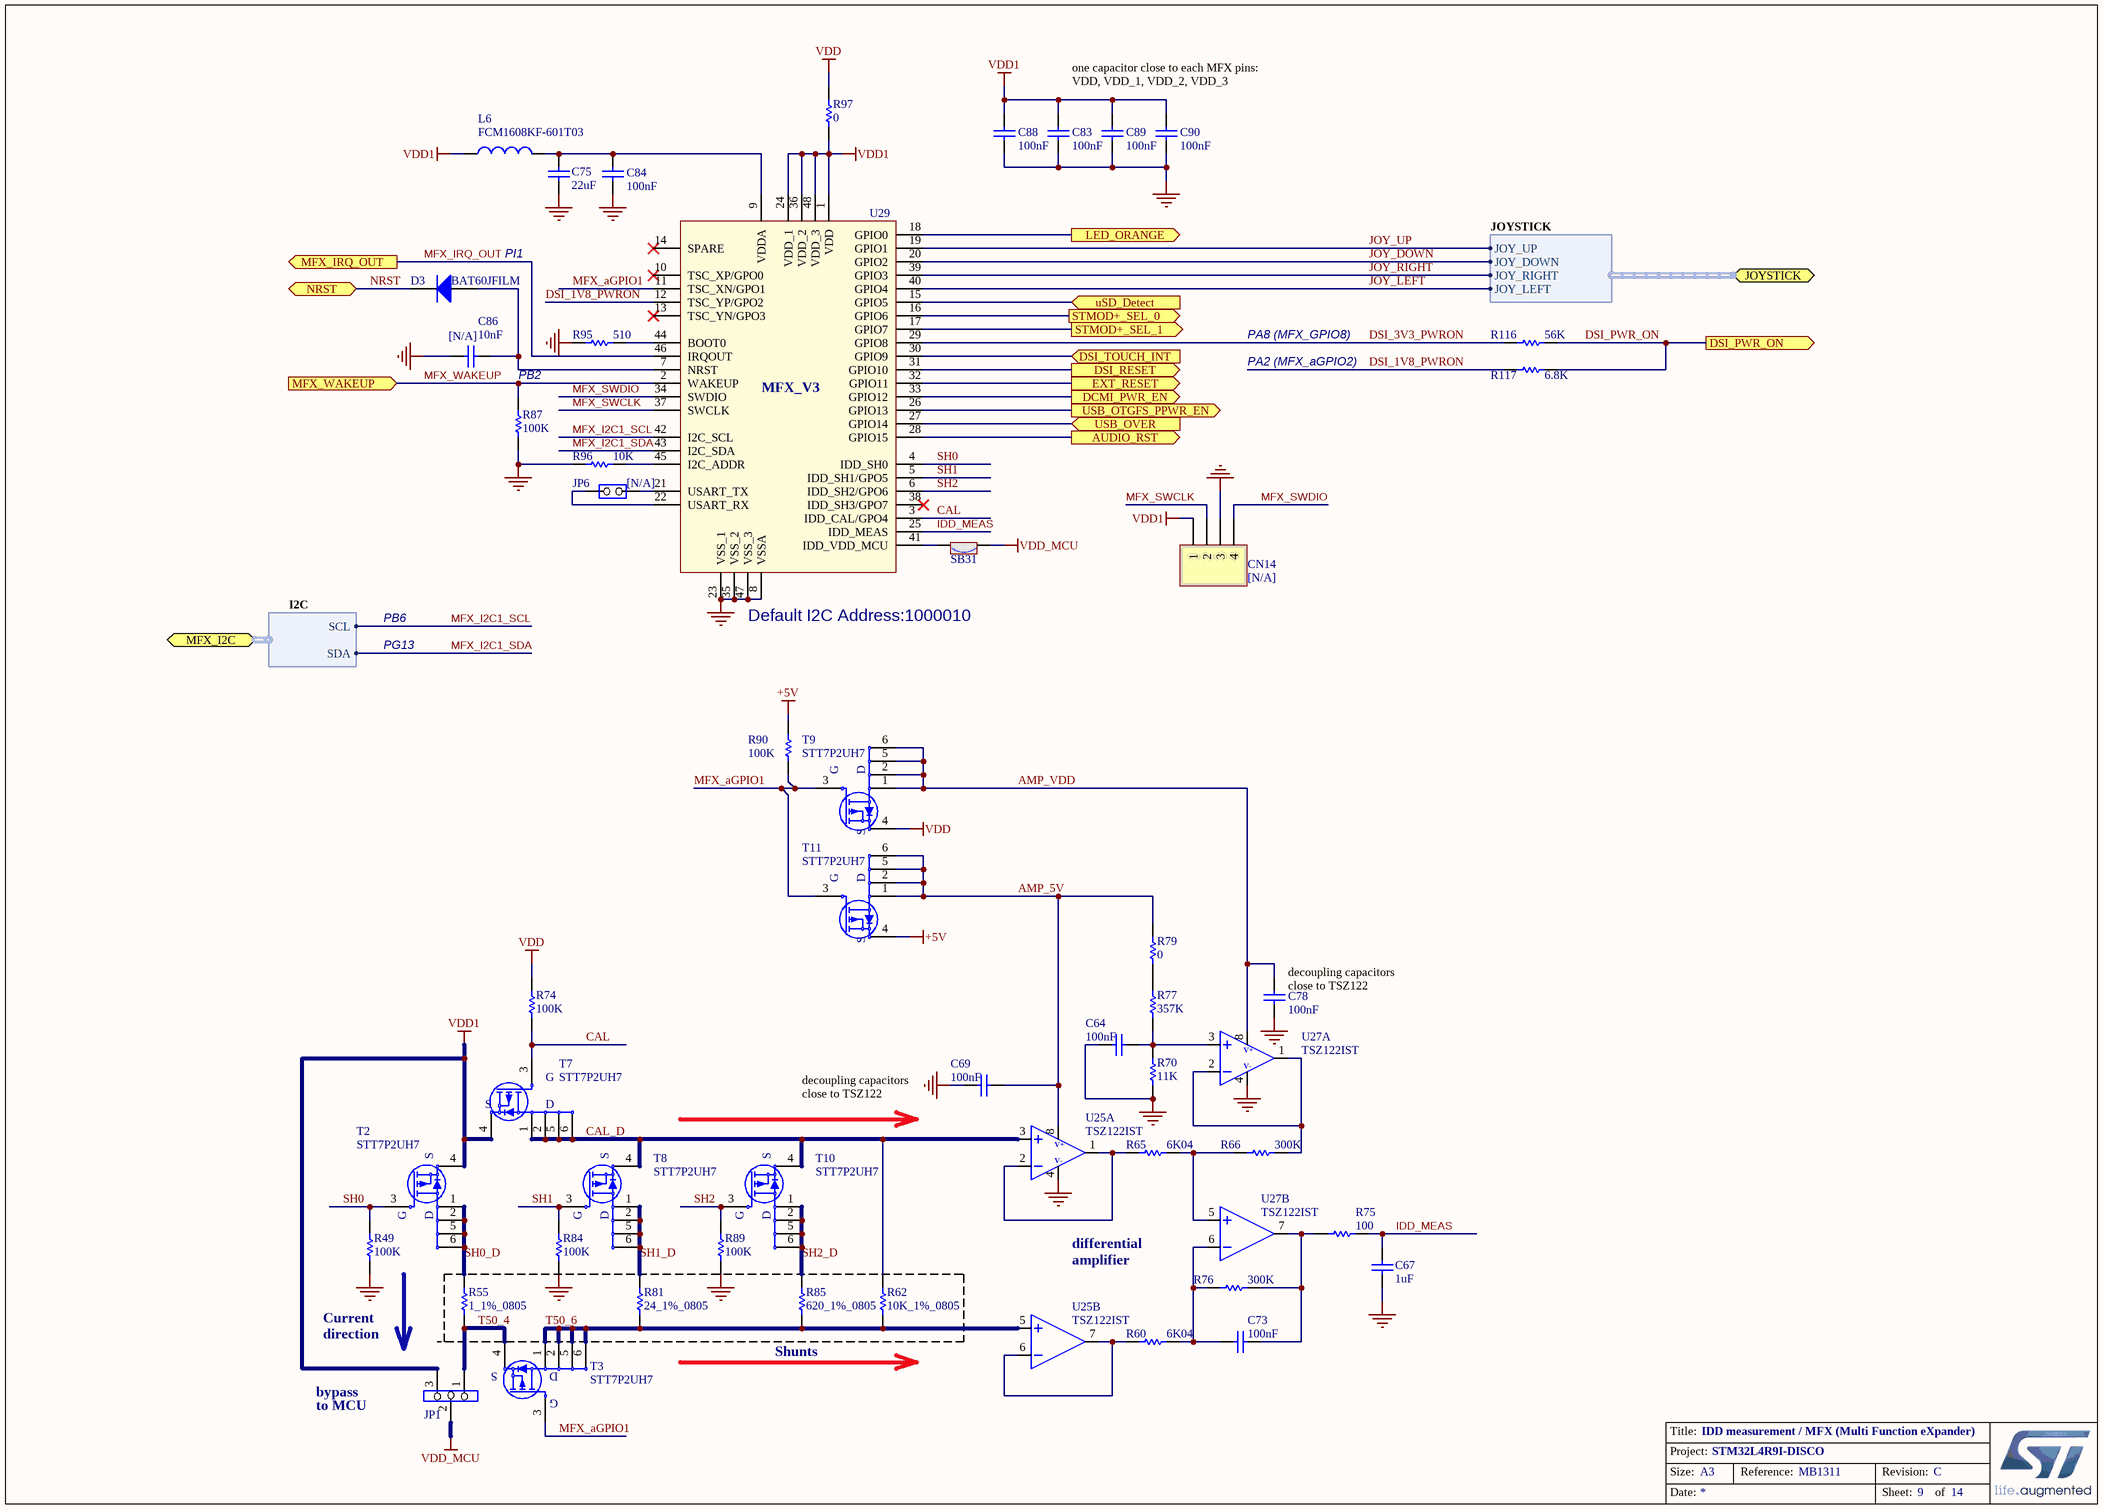
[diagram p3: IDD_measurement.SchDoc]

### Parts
C64  value 100nF  [C0603]  (hidden comment: CC0603KRX7R7BB104)
C67  value 1uF  [C0603]  (hidden comment: CC0603KRX5R7BB105)
C69  value 100nF  [C0603]  (hidden comment: CC0603KRX7R7BB104)
C73  value 100nF  [C0603]  (hidden comment: CC0603KRX7R7BB104)
C75  value 22uF  [CPOL_TAJ-A_1206_H180]  (hidden comment: GRM31CR61C226KE15L)
C78  value 100nF  [C0603]  (hidden comment: CC0603KRX7R7BB104)
C83  value 100nF  [C0603]  (hidden comment: CC0603KRX7R7BB104)
C84  value 100nF  [C0603]  (hidden comment: CC0603KRX7R7BB104)
C86  [N/A]  value 10nF  [C0603]
C88  value 100nF  [C0603]  (hidden comment: CC0603KRX7R7BB104)
C89  value 100nF  [C0603]  (hidden comment: CC0603KRX7R7BB104)
C90  value 100nF  [C0603]  (hidden comment: CC0603KRX7R7BB104)
CN14  [N/A]  [CON_988-JIUBABA_PHFS25-11-04-G0B115-T-1]
D3  BAT60JFILM  [DIO_SOD323]
JP1  3 PIN Jumper  [CON_988-JIUBABA_PHFS25-11-03-G0B115-T-1]  (value not drawn)
JP6  [N/A]  [CON_988-JIUBABA_PHFS25-11-02-G0B115-T-1]
L6  FCM1608KF-601T03  [L0603]
R49  value 100K  [R0603]  (hidden comment: RC0603FR-07100KL)
R55  1_1%_0805  [R0805]
R60  value 6K04  [R0603]  (hidden comment: RC0603FR-076K04L)
R62  10K_1%_0805  [R0805]
R65  value 6K04  [R0603]  (hidden comment: RC0603FR-076K04L)
R66  value 300K  [R0603]  (hidden comment: RC0603FR-07300KL)
R70  value 11K  [R0603]  (hidden comment: RC0603FR-0711KL)
R74  value 100K  [R0603]  (hidden comment: RC0603FR-07100KL)
R75  value 100  [R0603]  (hidden comment: RC0603JR-07100RL)
R76  value 300K  [R0603]  (hidden comment: RC0603FR-07300KL)
R77  value 357K  [R0603]  (hidden comment: RC0603FR-07357KL)
R79  value 0  [R0603]  (hidden comment: RC0603JR-070RL)
R81  24_1%_0805  [R0805]
R84  value 100K  [R0603]  (hidden comment: RC0603FR-07100KL)
R85  620_1%_0805  [R0805]
R87  value 100K  [R0603]  (hidden comment: RC0603FR-07100KL)
R89  value 100K  [R0603]  (hidden comment: RC0603FR-07100KL)
R90  value 100K  [R0603]  (hidden comment: RC0603FR-07100KL)
R95  value 510  [R0603]  (hidden comment: RC0603FR-07510RL)
R96  value 10K  [R0603]  (hidden comment: RC0603FR-0710KL)
R97  value 0  [R0603]  (hidden comment: RC0603JR-070RL)
R116  value 56K  [R0603]  (hidden comment: RC0603FR-0756KL)
R117  value 6.8K  [R0603]  (hidden comment: RC0603FR-076K8L)
SB31  Solder Bridge ON  [SOLDER-BRIDGE_R0603-0R]  (value not drawn)
T2  STT7P2UH7  [MOS_SOT23-6L]
T3  STT7P2UH7  [MOS_SOT23-6L]
T7  STT7P2UH7  [MOS_SOT23-6L]
T8  STT7P2UH7  [MOS_SOT23-6L]
T9  STT7P2UH7  [MOS_SOT23-6L]
T10  STT7P2UH7  [MOS_SOT23-6L]
T11  STT7P2UH7  [MOS_SOT23-6L]
U25  TSZ122IST  [ICC_MINISO8_3X3_P065]  (parts A,B of 2)
U27  TSZ122IST  [ICC_MINISO8_3X3_P065]  (parts A,B of 2)
U29  STM32L152CCT6  [ICC_LQFP48_7X7_P050]  (value not drawn)

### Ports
AUDIO_RST (out), DCMI_PWR_EN (out), DSI_PWR_ON (out), DSI_RESET (out), DSI_TOUCH_INT (in), EXT_RESET (out), JOYSTICK (harness JOYSTICK), LED_ORANGE (out), MFX_I2C (harness I2C), MFX_IRQ_OUT (out), MFX_WAKEUP (in), NRST, STMOD+_SEL_0 (out), STMOD+_SEL_1 (out), USB_OTGFS_PPWR_EN (out), USB_OVER (in), uSD_Detect (in)

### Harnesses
I2C: SDA, SCL
JOYSTICK: JOY_UP, JOY_DOWN, JOY_RIGHT, JOY_LEFT

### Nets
+5V: R90.2 T11.4(S)
GND: C64.1 C67.2 C69.1 C75.1 C78.2 C83.2 C84.2 C86.2 C88.2 C89.2 C90.2 CN14.3 R49.1 R70.2 R84.1 R87.1 R89.1 R95.2 R96.2 U25.4 U27.4 U29.8(VSSA) U29.23(VSS_1) U29.35(VSS_2) U29.47(VSS_3)
VDD: R74.2 R97.1 T9.4(S)
VDD1: C83.1 C88.1 C89.1 C90.1 CN14.1 JP1.3 L6.1 R97.2 T2.4(S) T7.4(S) U29.1(VDD) U29.24(VDD_1) U29.36(VDD_2) U29.48(VDD_3)
VDD_MCU: JP1.2 SB31.1
AMP_5V: C69.2 R79.2 T11.1(S) T11.2(S) T11.5(D) T11.6(D) U25.8
AMP_VDD: C78.1 T9.1(S) T9.2(S) T9.5(D) T9.6(D) U27.8
CAL: R74.1 T7.3(G) U29.3(IDD_CAL/GPO4)
CAL_D: R62.2 T7.1(S) T7.2(S) T7.5(D) T7.6(D) T8.4(S) T10.4(S) U25.3
DCMI_PWR_EN: U29.33(GPIO12) ; port DCMI_PWR_EN
DSI_1V8_PWRON: R117.1 U29.12(TSC_YP/GPO2)
DSI_3V3_PWRON: R116.1 U29.29(GPIO8)
DSI_PWR_ON: R116.2 R117.2 ; port DSI_PWR_ON
IDD_MEAS: C67.1 R75.1 U29.25(IDD_MEAS)
JOY_DOWN: U29.20(GPIO2) ; port JOYSTICK.JOY_DOWN
JOY_LEFT: U29.40(GPIO4) ; port JOYSTICK.JOY_LEFT
JOY_RIGHT: U29.39(GPIO3) ; port JOYSTICK.JOY_RIGHT
JOY_UP: U29.19(GPIO1) ; port JOYSTICK.JOY_UP
MFX_aGPIO1: R90.1 T3.3(G) T9.3(G) T11.3(G) U29.11(TSC_XN/GPO1)
MFX_I2C1_SCL: U29.42(I2C_SCL) ; port MFX_I2C.SCL  [project net DCMI_I2C1_SCL]
MFX_I2C1_SDA: U29.43(I2C_SDA) ; port MFX_I2C.SDA  [project net DCMI_I2C1_SDA]
MFX_IRQ_OUT: U29.46(IRQOUT) ; port MFX_IRQ_OUT
MFX_SWCLK: CN14.2 U29.37(SWCLK)
MFX_SWDIO: CN14.4 U29.34(SWDIO)
MFX_WAKEUP: R87.2 U29.2(WAKEUP) ; port MFX_WAKEUP
NRST: D3.2(K) ; port NRST  [project net DCMI_NRST]
PMOD_SEL_0: U29.16(GPIO6) ; port STMOD+_SEL_0
PMOD_SEL_1: U29.17(GPIO7) ; port STMOD+_SEL_1
SH0: R49.2 T2.3(G) U29.4(IDD_SH0)
SH0_D: R55.2 T2.1(S) T2.2(S) T2.5(D) T2.6(D)
SH1: R84.2 T8.3(G) U29.5(IDD_SH1/GPO5)
SH1_D: R81.2 T8.1(S) T8.2(S) T8.5(D) T8.6(D)
SH2: R89.2 T10.3(G) U29.6(IDD_SH2/GPO6)
SH2_D: R85.2 T10.1(S) T10.2(S) T10.5(D) T10.6(D)
T50_4: JP1.1 R55.1 T3.4(S)
T50_6: R62.1 R81.1 R85.1 T3.1(S) T3.2(S) T3.5(D) T3.6(D) U25.5
TOUCH_INT: U29.30(GPIO9) ; port DSI_TOUCH_INT
USB_OTGFS_OVRCR: U29.27(GPIO14) ; port USB_OVER
uSD_Detect: U29.15(GPIO5) ; port uSD_Detect
NetC64_2: C64.2 R70.1 R77.2 U27.3
NetC73_1: C73.1 R60.1 R76.1 U27.6
NetC73_2: C73.2 R75.2 R76.2 U27.7
NetC75_2: C75.2 C84.1 L6.2 U29.9(VDDA)
NetC86_1: C86.1 D3.1(A) U29.7(NRST)
NetCN4_57: U29.31(GPIO10) ; port DSI_RESET
NetJP6_1: JP6.1(COMMON) U29.22(USART_RX)
NetJP6_2: JP6.2(NO) U29.21(USART_TX)
NetR3_1: U29.18(GPIO0) ; port LED_ORANGE
NetR41_2: U29.26(GPIO13) ; port USB_OTGFS_PPWR_EN
NetR60_2: R60.2 U25.6 U25.7
NetR65_1: R65.1 R66.1 U27.5
NetR65_2: R65.2 U25.1 U25.2
NetR66_2: R66.2 U27.1 U27.2
NetR77_1: R77.1 R79.1
NetR83_2: U29.28(GPIO15) ; port AUDIO_RST
NetR95_1: R95.1 U29.44(BOOT0)
NetR96_1: R96.1 U29.45(I2C_ADDR)
NetR112_2: U29.32(GPIO11) ; port EXT_RESET
NetSB31_2: SB31.2 U29.41(IDD_VDD_MCU)

Not connected (* = marked no-connect by the designer): U29 10(TSC_XP/GPO0)* 13(TSC_YN/GPO3)* 14(SPARE)* 38(IDD_SH3/GPO7)*

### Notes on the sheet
- one capacitor close to each MFX pins: VDD, VDD_1, VDD_2, VDD_3
- PI1
- PB2
- PA8 (MFX_GPIO8)
- PA2 (MFX_aGPIO2)
- PG13
- PB6
- (near U29) Default I2C Address:1000010
- (near C78) decoupling capacitors
  close to TSZ122
- decoupling capacitors
  close to TSZ122
- differential
  amplifier
- Current direction
- Shunts
- to MCU
- bypass

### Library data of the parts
C64 C69 C73 C78 C83 C84 C88-C90 = Cap: as C3 on sheet Camera
C67 = Cap: Capacitor,1uF,0603,16V,10%,X5R,YAGEO; Ordered by: Subcon
C75 = Cap_22µF_X5R_16V_10%_1206: as C46 on sheet Camera
C86 = Cap: Capacitor,10nF,0603,50V,10%,X7R,YAGEO;; Manuf_Part_1: CC0603KRX7R9BB103; Ordered by: Subcon
CN14 = Header 4: Header, 4-Pin; SOFER_FP: HDR_1X4_2R54; Ordered by: Subcon
D3 = BAT60JFILM: Provided: STM; ECCN_US/EU: EAR99/NEC; Ref St: 9151097
JP1 = Jumper3: Jumper 3 pins; Manuf_1: lyconn; Manuf_Part_1: 313103S111116; Ordered by: Subcon
JP6 = JP2: 2 PIN Jumper; Manuf_1: lyconn; Manuf_Part_1: 313102S111116; Ordered by: Subcon; Assembly: with jumper
L6 = BEAD_600R_350MA_0603: Bead,600R,350mA,0603,FCM1608KF-601T03,Tai-tech; Manuf_2: TDK; Manuf_Part_2: MPZ1608S300A; Value: 100uH; Comment_1: bead,30R,5A,0603,MPZ1608S300A,TDK; Ordered by: Subcon
R49 R74 R84 R87 R89 R90 = res1: Resistor,100K,0603,1%,YAGEO; Ordered by: Subcon; ECCN_US/EU: NA
R55 = Res_1_1%_0805: Resistor,1,0805,1%,YAGEO; Manuf_Part_1: RC0805FR-071RL; Value: 1; Ordered by: Subcon
R60 R65 = res1: Resistor,6.04K,0603,1%,YAGEO; Ordered by: Subcon; ECCN_US/EU: NA
R62 = Res_10K_1%_0805: Resistor,10K,0805,1%,YAGEO; Manuf_Part_1: RC0805FR-0710KL; Ordered by: Subcon
R66 R76 = res1: Resistor,300K,0603,1%,YAGEO; Ordered by: Subcon; ECCN_US/EU: NA
R70 = res1: Resistor,11K,0603,1%,YAGEO; Ordered by: Subcon; ECCN_US/EU: NA
R75 = res1: Resistor, 100 ,0603,1%,YAGEO; Ordered by: Subcon; ECCN_US/EU: NA
R77 = res1: Resistor,357K,0603,1%,YAGEO; Ordered by: Subcon; ECCN_US/EU: NA
R79 R97 = res1: Resistor, 0 ,0603,1%,YAGEO; Ordered by: Subcon; ECCN_US/EU: NA
R81 = Res_24_1%_0805: Resistor,24,0805,1%,YAGEO; Manuf_Part_1: RC0805FR-0724RL; Value: 24; Ordered by: Subcon
R85 = Res_620_1%_0805: Resistor,620,0805,1%,YAGEO; Manuf_Part_1: RC0805FR-07620RL; Value: 620; Ordered by: Subcon
R95 = res1: Resistor,510R,0603,1%,YAGEO; Ordered by: Subcon; ECCN_US/EU: NA
R96 = res1: Resistor,10K,0603,1%,YAGEO; Ordered by: Subcon; ECCN_US/EU: NA
R116 = res1: Resistor,56K,0603,1%,YAGEO; Ordered by: Subcon; ECCN_US/EU: NA
R117 = res1: Resistor,6.8K,0603,1%,YAGEO; Ordered by: Subcon; ECCN_US/EU: NA
SB31 = SB_ON: as SB2 on sheet Arduino_ Connectors
T2 = STT7P2UH7: STripFET VII DeepGATE Power MOSFET, P-CHANNEL 20 V, 0.0146, 7 A - SOT23-6L; Manuf_1: STM; Provided: ST; Ref St: xxxxxxxx; ECCN_US/EU: EAR99/NEC; Comments: exclusive with T8
T3 T7 T9 T11 = STT7P2UH7: STripFET VII DeepGATE Power MOSFET, P-CHANNEL 20 V, 0.0146, 7 A - SOT23-6L; Manuf_1: STM; Provided: ST; Ref St: xxxxxxxx; ECCN_US/EU: EAR99/NEC; Comments: exclusive with T2
T8 = STT7P2UH7: STripFET VII DeepGATE Power MOSFET, P-CHANNEL 20 V, 0.0146, 7 A - SOT23-6L; Manuf_1: STM; Provided: ST; Ref St: xxxxxxxx; ECCN_US/EU: EAR99/NEC; Comments: exclusive with T3
T10 = STT7P2UH7: STripFET VII DeepGATE Power MOSFET, P-CHANNEL 20 V, 0.0146, 7 A - SOT23-6L; Manuf_1: STM; Provided: ST; Ref St: xxxxxxxx; ECCN_US/EU: EAR99/NEC; Comments: exclusive with T4
U25 U27 = TSZ122IST: Very high accuracy (5 礦) zero drift 5 V dual OpAmp; Manuf_1: STM; ECCN_US/EU: EAR99/NEC; Provided: ST; Ref St: xxxxxxxxx
U29 = MFX: Multifunction expander; Manuf_1: STM

## Sheet LCD.SchDoc: LCD Interface
size A3; Date: 18/07/2017; Author: P.A.; CompanyName: STMicroelectronics; Organization: Microcontrollers Division; Address1: 12, Rue Jules HOROWITZ; Address2: 38019 Grenoble; Address3: FRANCE; DocumentNumber: MB1311; Revision: C; SheetNumber: 8; SheetTotal: 14; Project: STM32L4R9I-DISCO
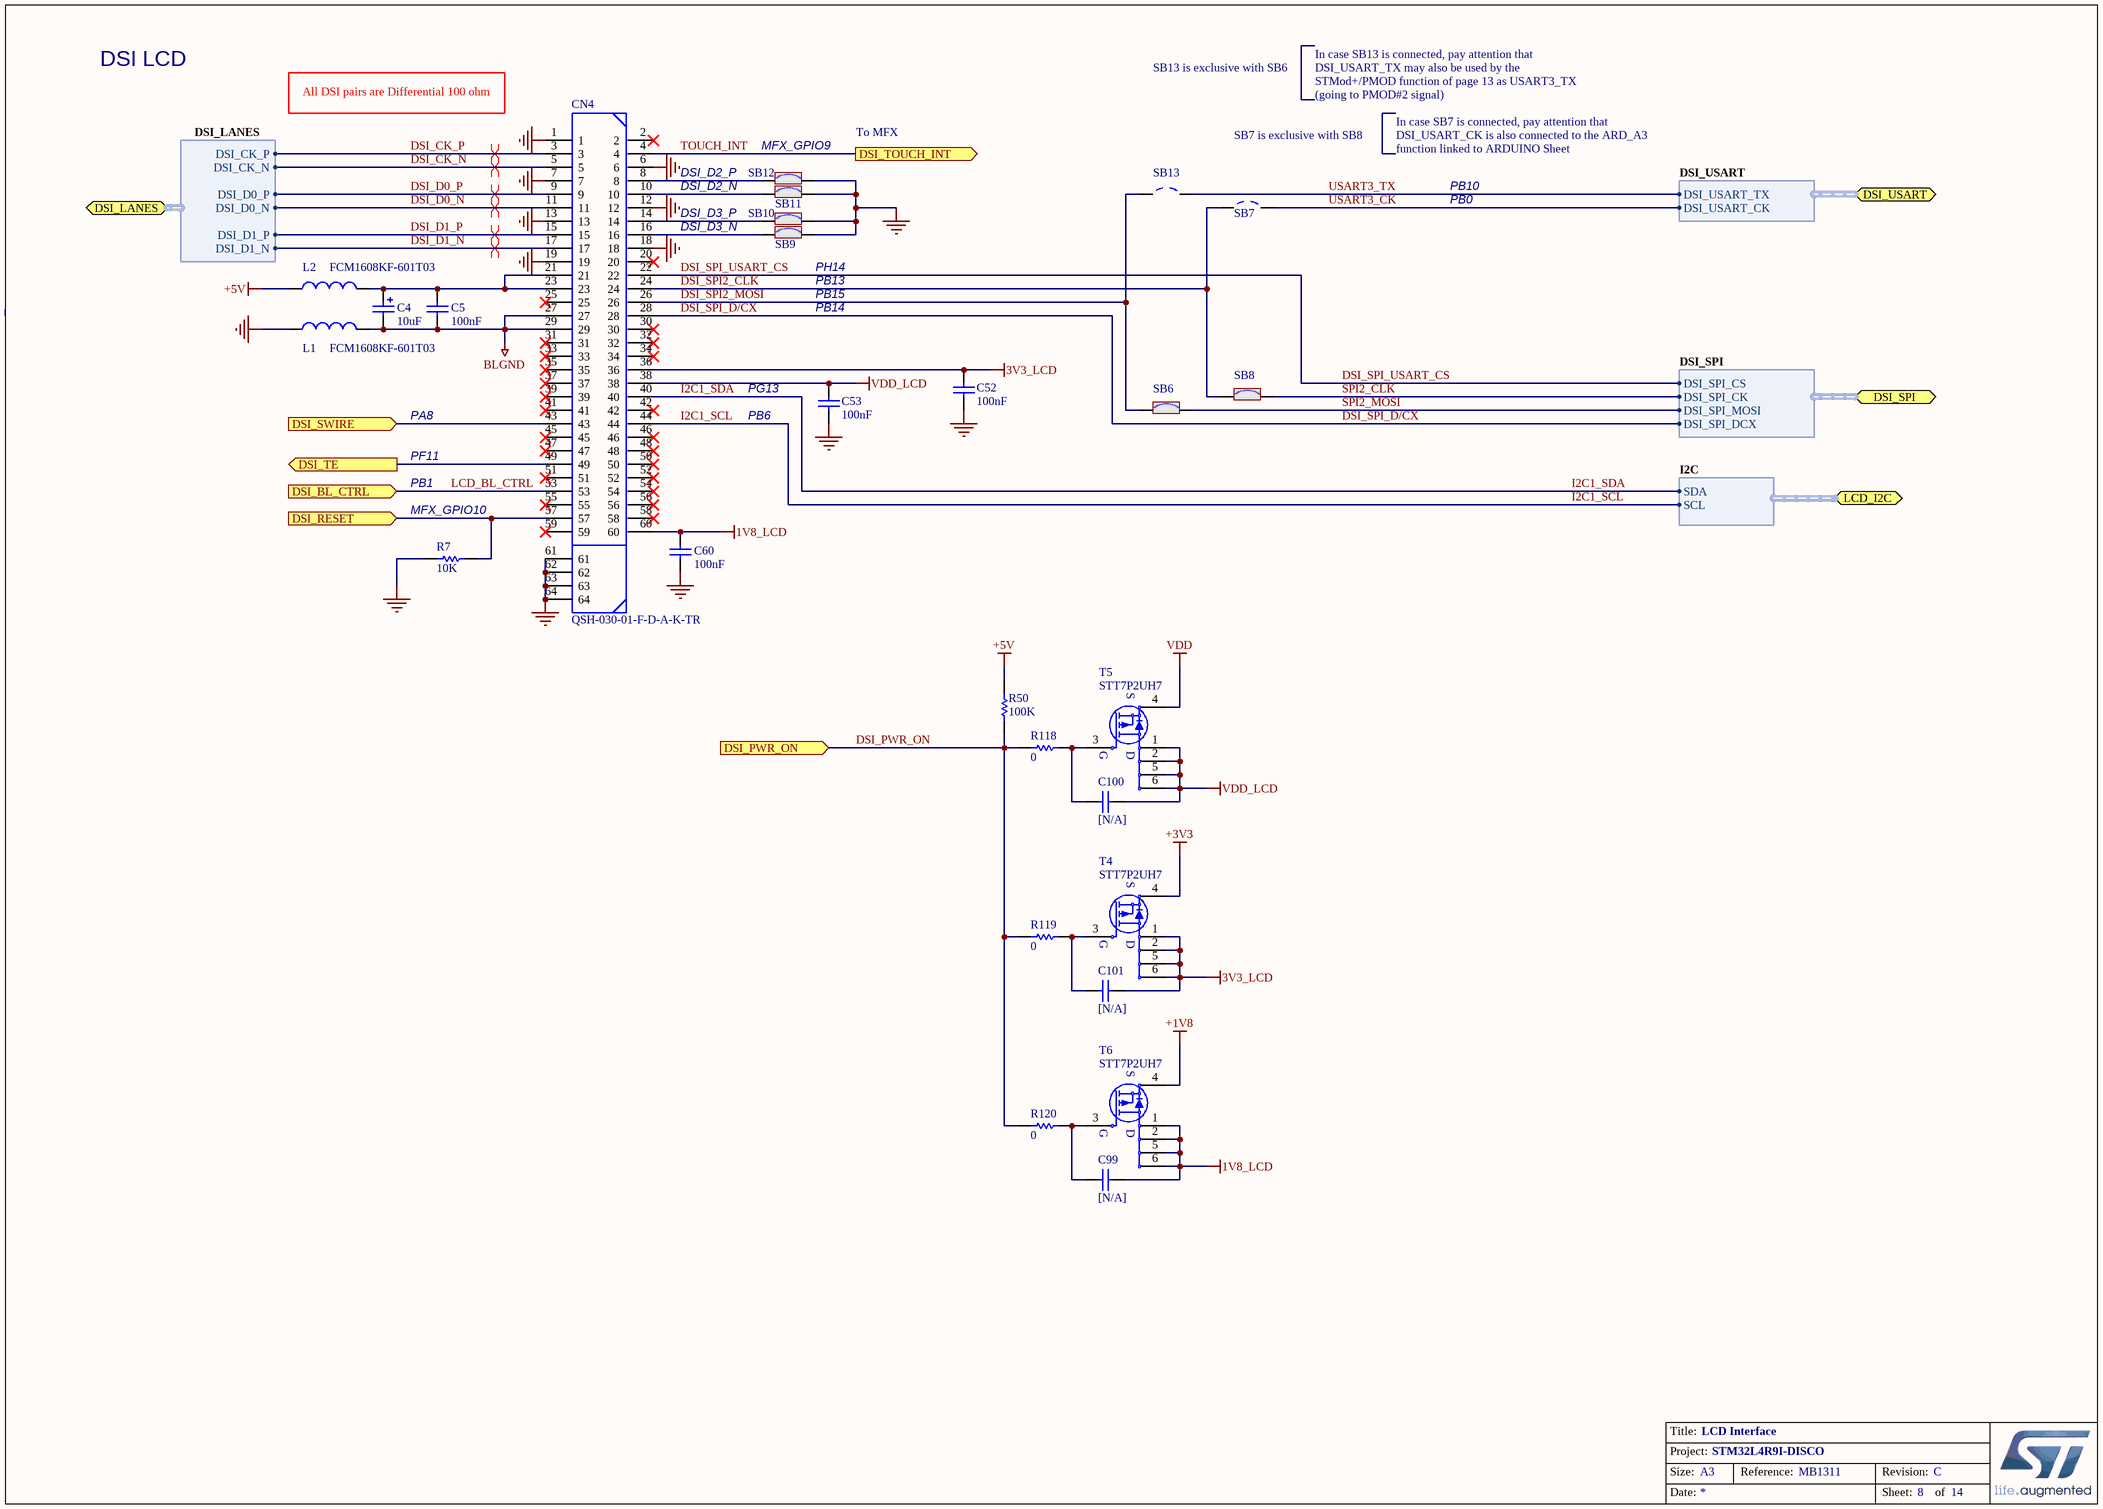
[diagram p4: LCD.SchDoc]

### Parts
C4  value 10uF  [CPOL_TAJ-A_1206_H180]  (hidden comment: TAJA106K016R)
C5  value 100nF  [C0603]  (hidden comment: CC0603KRX7R7BB104)
C52  value 100nF  [C0603]  (hidden comment: CC0603KRX7R7BB104)
C53  value 100nF  [C0603]  (hidden comment: CC0603KRX7R7BB104)
C60  value 100nF  [C0603]  (hidden comment: CC0603KRX7R7BB104)
C99  [N/A]  [C0603]
C100  [N/A]  [C0603]
C101  [N/A]  [C0603]
CN4  QSH-030-01-F-D-A-K-TR  [CON_SAMTEC_QSH-030-01-F-D-A]
L1  FCM1608KF-601T03  [L0603]
L2  FCM1608KF-601T03  [L0603]
R7  value 10K  [R0603]  (hidden comment: RC0603FR-0710KL)
R50  value 100K  [R0603]  (hidden comment: RC0603FR-07100KL)
R118  value 0  [R0603]  (hidden comment: RC0603JR-070RL)
R119  value 0  [R0603]  (hidden comment: RC0603JR-070RL)
R120  value 0  [R0603]  (hidden comment: RC0603JR-070RL)
SB6  Solder Bridge ON  [SOLDER-BRIDGE_R0603-0R]  (value not drawn)
SB7  Solder Bridge OFF  [SOLDER-BRIDGE_R0603-0R]  (value not drawn)
SB8  Solder Bridge ON  [SOLDER-BRIDGE_R0603-0R]  (value not drawn)
SB9  Solder Bridge ON  [SOLDER-BRIDGE_R0603-0R]  (value not drawn)
SB10  Solder Bridge ON  [SOLDER-BRIDGE_R0603-0R]  (value not drawn)
SB11  Solder Bridge ON  [SOLDER-BRIDGE_R0603-0R]  (value not drawn)
SB12  Solder Bridge ON  [SOLDER-BRIDGE_R0603-0R]  (value not drawn)
SB13  Solder Bridge OFF  [SOLDER-BRIDGE_R0603-0R]  (value not drawn)
T4  STT7P2UH7  [MOS_SOT23-6L]
T5  STT7P2UH7  [MOS_SOT23-6L]
T6  STT7P2UH7  [MOS_SOT23-6L]

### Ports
DSI_BL_CTRL (in), DSI_LANES (harness DSI_LANES), DSI_PWR_ON (in), DSI_RESET (in), DSI_SPI (harness DSI_SPI), DSI_SWIRE (in), DSI_TE (out), DSI_TOUCH_INT (out), DSI_USART (harness DSI_USART), LCD_I2C (harness I2C)

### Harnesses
I2C: SDA, SCL
DSI_USART: DSI_USART_CK, DSI_USART_TX
DSI_SPI: DSI_SPI_CS, DSI_SPI_MOSI, DSI_SPI_CK, DSI_SPI_DCX
DSI_LANES: DSI_CK_P, DSI_CK_N, DSI_D0_P, DSI_D0_N, DSI_D1_N, DSI_D1_P

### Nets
1V8_LCD: C60.1 C99.2 CN4.60 T6.1(S) T6.2(S) T6.5(D) T6.6(D)
3V3_LCD: C52.2 C101.2 CN4.36 T4.1(S) T4.2(S) T4.5(D) T4.6(D)
+1V8: T6.4(S)
+3V3: T4.4(S)
+5V: L2.1 R50.1
BLGND: C4.2 C5.2 CN4.27 CN4.29 L1.2
GND: C52.1 C53.1 C60.2 CN4.1 CN4.6 CN4.7 CN4.12 CN4.13 CN4.18 CN4.19 CN4.61 CN4.62 CN4.63 CN4.64 L1.1 R7.1 SB9.2 SB10.2 SB11.2 SB12.2
VDD: T5.4(S)
VDD_LCD: C53.2 C100.2 CN4.38 T5.1(S) T5.2(S) T5.5(D) T5.6(D)
DCMI_CLK: CN4.43 ; port DSI_SWIRE
DSI_CK_N: CN4.5 ; port DSI_LANES.DSI_CK_N
DSI_CK_P: CN4.3 ; port DSI_LANES.DSI_CK_P
DSI_D0_N: CN4.11 ; port DSI_LANES.DSI_D0_N
DSI_D0_P: CN4.9 ; port DSI_LANES.DSI_D0_P
DSI_D1_N: CN4.17 ; port DSI_LANES.DSI_D1_N
DSI_D1_P: CN4.15 ; port DSI_LANES.DSI_D1_P
DSI_PWR_ON: R50.2 R118.2 R119.2 R120.2 ; port DSI_PWR_ON
DSI_SPI2_CLK: CN4.24 SB7.1 SB8.1
DSI_SPI2_MOSI: CN4.26 SB6.1 SB13.1
DSI_SPI_D/CX: CN4.28 ; port DSI_SPI.DSI_SPI_DCX  [project net ARD_D12]
DSI_SPI_USART_CS: CN4.22 ; port DSI_SPI.DSI_SPI_CS
DSI_TE: CN4.49 ; port DSI_TE
I2C1_SCL: CN4.44 ; port LCD_I2C.SCL  [project net DCMI_I2C1_SCL]
I2C1_SDA: CN4.40 ; port LCD_I2C.SDA  [project net DCMI_I2C1_SDA]
LCD_BL_CTRL: CN4.53 ; port DSI_BL_CTRL  [project net DSI_BL_CTRL]
SPI2_CLK: SB8.2 ; port DSI_SPI.DSI_SPI_CK  [project net ARD_D13]
SPI2_MOSI: SB6.2 ; port DSI_SPI.DSI_SPI_MOSI  [project net ARD_D11]
TOUCH_INT: CN4.4 ; port DSI_TOUCH_INT
USART3_CK: SB7.2 ; port DSI_USART.DSI_USART_CK  [project net ARD_A3]
USART3_TX: SB13.2 ; port DSI_USART.DSI_USART_TX
NetC4_1: C4.1 C5.1 CN4.21 CN4.23 L2.2
NetC99_1: C99.1 R120.1 T6.3(G)
NetC100_1: C100.1 R118.1 T5.3(G)
NetC101_1: C101.1 R119.1 T4.3(G)
NetCN4_8: CN4.8 SB12.1
NetCN4_10: CN4.10 SB11.1
NetCN4_14: CN4.14 SB10.1
NetCN4_16: CN4.16 SB9.1
NetCN4_57: CN4.57 R7.2 ; port DSI_RESET

Not connected (* = marked no-connect by the designer): CN4 2* 20* 25* 30* 31* 32* 33* 34* 35* 37* 39* 41* 42* 45* 46* 47* 48* 50* 51* 52* 54* 55* 56* 58* 59*

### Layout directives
differential pair: DSI_CK_N, DSI_CK_P, DSI_D0_N, DSI_D0_P, DSI_D1_N, DSI_D1_P

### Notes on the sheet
- DSI LCD
- All DSI pairs are Differential 100 ohm
- SB13 is exclusive with SB6
- In case SB13 is connected, pay attention that DSI_USART_TX may also be used by the
  STMod+/PMOD function of page 13 as USART3_TX (going to PMOD#2 signal)
- DSI_D2_P
- MFX_GPIO9
- To MFX
- SB7 is exclusive with SB8
- In case SB7 is connected, pay attention that DSI_USART_CK is also connected to the ARD_A3 function linked to ARDUINO Sheet
- DSI_D2_N
- DSI_D3_P
- DSI_D3_N
- PB10
- PB0
- PB14
- PB15
- PH14
- PB13
- PA8
- PG13
- PB6
- PB1
- PF11
- (near R7) MFX_GPIO10

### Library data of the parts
C4 = Cap Pol1: TAN Capacitor,10uF,10%,16V,A Type,AVX; Ordered by: Subcon; ECCN_US/EU: NA
C5 C52 C53 C60 = Cap: as C3 on sheet Camera
C99-C101 = Cap: as C48 on sheet Arduino_ Connectors
CN4 = QSH-030-01-F-D-A: HIGH SPEED SOCKET STRIP, .5mm PITCH, 60 PINS; MANUFACTURER: SAMTEC; PCB DECAL: QSH-030-01-X-D-A
L1 L2 = Inductor: 100uH Bead; Manuf_1: Tai-tech; Ordered by: Subcon; ECCN_US/EU: NA
R7 = res1: as R96 on sheet IDD_measurement
R50 = res1: as R49 on sheet IDD_measurement
R118-R120 = res1: as R79 on sheet IDD_measurement
SB6 SB8 = SB_ON: Manuf_1: YAGEO; Manuf_Part_1: RC0603JR-070RL; Solder: YES; Ordered By: Subcon; Fitted: NO
SB7 SB13 = SB_OFF: Solder: NO
SB9-SB12 = SB_ON: as SB2 on sheet Arduino_ Connectors
T4-T6 = STT7P2UH7: as T3 on sheet IDD_measurement

## Sheet MCU.SchDoc: MCU
size A3; Author: P.A.; CompanyName: STMicroelectronics; Organization: Microcontrollers Division; Address1: 12, Rue Jules HOROWITZ; Address2: 38019 Grenoble; Address3: FRANCE; DocumentNumber: MB1311; Revision: C; SheetNumber: 10; SheetTotal: 14; Project: STM32L4R9I-DISCO
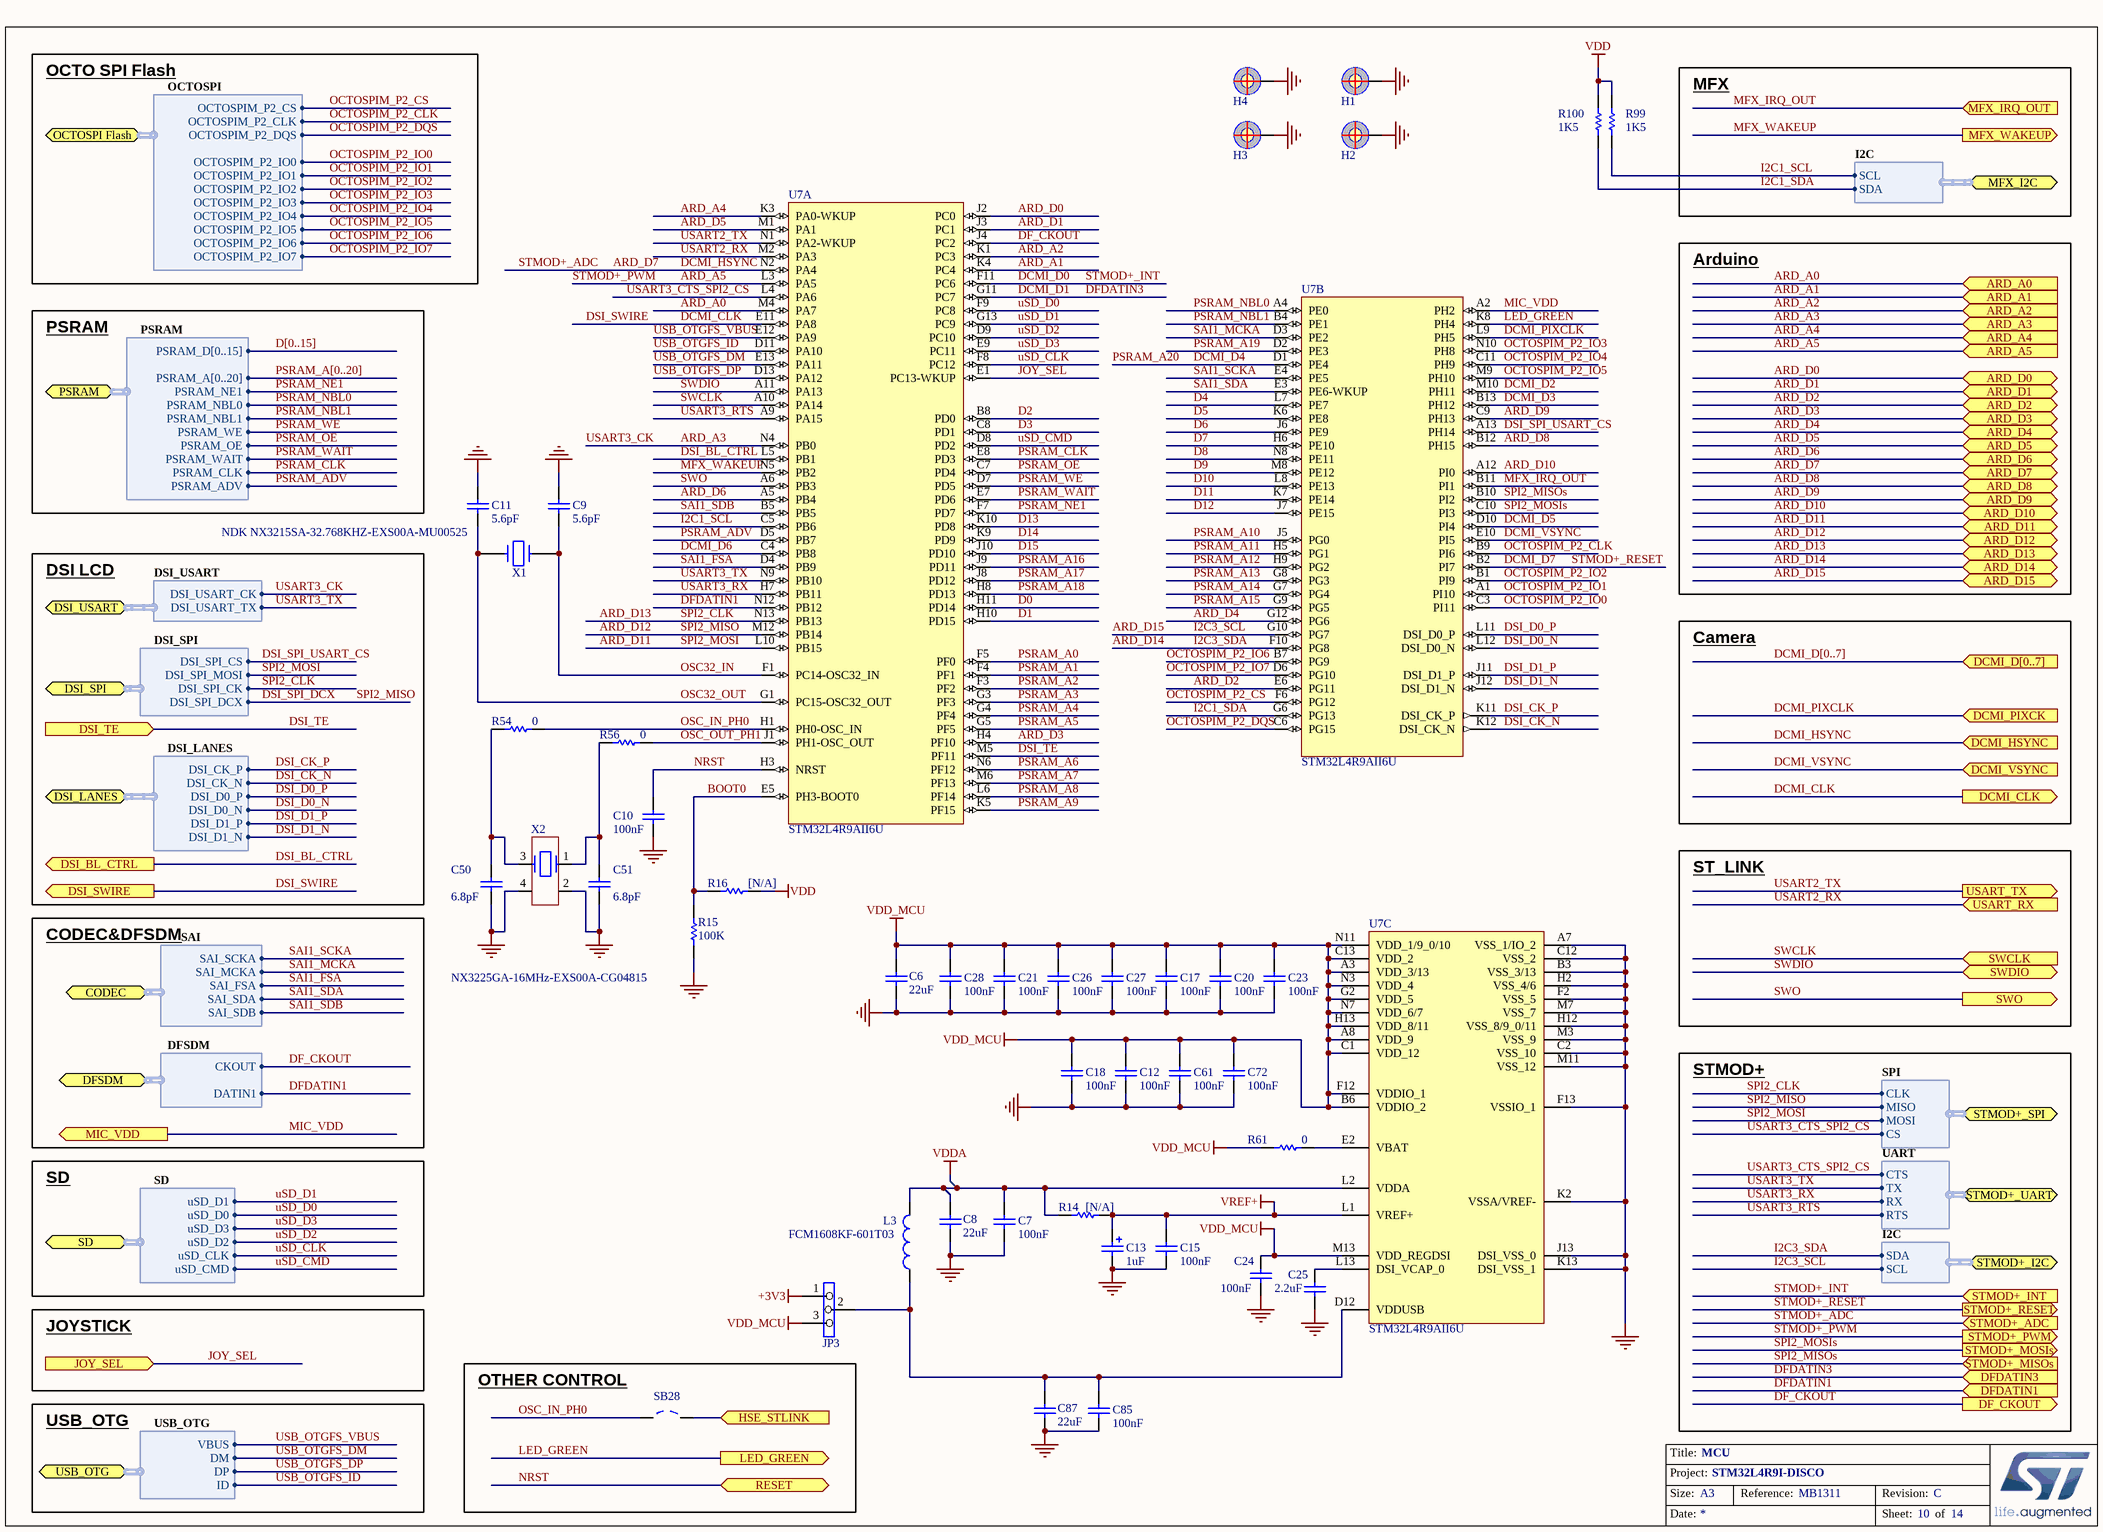
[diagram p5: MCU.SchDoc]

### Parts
C6  value 22uF  [CPOL_TAJ-A_1206_H180]  (hidden comment: GRM31CR61C226KE15L)
C7  value 100nF  [C0603]  (hidden comment: CC0603KRX7R7BB104)
C8  value 22uF  [CPOL_TAJ-A_1206_H180]  (hidden comment: GRM31CR61C226KE15L)
C9  5.6pF  [C0603]
C10  value 100nF  [C0603]  (hidden comment: CC0603KRX7R7BB104)
C11  5.6pF  [C0603]
C12  value 100nF  [C0603]  (hidden comment: CC0603KRX7R7BB104)
C13  value 1uF  [CPOL_TAJ-A_1206_H180]  (hidden comment: TAJA105K016R)
C15  value 100nF  [C0603]  (hidden comment: CC0603KRX7R7BB104)
C17  value 100nF  [C0603]  (hidden comment: CC0603KRX7R7BB104)
C18  value 100nF  [C0603]  (hidden comment: CC0603KRX7R7BB104)
C20  value 100nF  [C0603]  (hidden comment: CC0603KRX7R7BB104)
C21  value 100nF  [C0603]  (hidden comment: CC0603KRX7R7BB104)
C23  value 100nF  [C0603]  (hidden comment: CC0603KRX7R7BB104)
C24  value 100nF  [C0603]  (hidden comment: CC0603KRX7R7BB104)
C25  2.2uF  [C0603]
C26  value 100nF  [C0603]  (hidden comment: CC0603KRX7R7BB104)
C27  value 100nF  [C0603]  (hidden comment: CC0603KRX7R7BB104)
C28  value 100nF  [C0603]  (hidden comment: CC0603KRX7R7BB104)
C50  6.8pF  [C0603]
C51  6.8pF  [C0603]
C61  value 100nF  [C0603]  (hidden comment: CC0603KRX7R7BB104)
C72  value 100nF  [C0603]  (hidden comment: CC0603KRX7R7BB104)
C85  value 100nF  [C0603]  (hidden comment: CC0603KRX7R7BB104)
C87  value 22uF  [CPOL_TAJ-A_1206_H180]  (hidden comment: GRM31CR61C226KE15L)
H1  POSITION HOLE  [PTH_350_700]  (value not drawn)
H2  POSITION HOLE  [PTH_350_700]  (value not drawn)
H3  POSITION HOLE  [PTH_350_700]  (value not drawn)
H4  POSITION HOLE  [PTH_350_700]  (value not drawn)
JP3  Jumper3  [CON_988-JIUBABA_PHFS25-11-03-G0B115-T-1]  (value not drawn)
L3  FCM1608KF-601T03  [L0603]
R14  [N/A]  [R0603]
R15  value 100K  [R0603]  (hidden comment: RC0603FR-07100KL)
R16  [N/A]  [R0603]
R54  0  [R0603]
R56  0  [R0603]
R61  value 0  [R0603]  (hidden comment: RC0603JR-070RL)
R99  value 1K5  [R0603]  (hidden comment: RC0603FR-071K5L)
R100  value 1K5  [R0603]  (hidden comment: RC0603FR-071K5L)
SB28  Solder Bridge OFF  [SOLDER-BRIDGE_R0603-0R]  (value not drawn)
U7  STM32L4R9AII6U  [ICC_UFBGA169_7X7_P050]  (parts A,B,C of 3)
X1  NDK NX3215SA-32.768KHZ-EXS00A-MU00525  [CRY_NX3215SA_2P]
X2  NX3225GA-16MHz-EXS00A-CG04815  [CRY_NX3225HA_4P]

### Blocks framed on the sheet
OTHER CONTROL: SB28

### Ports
ARD_A0 (in), ARD_A1 (in), ARD_A2 (in), ARD_A3 (in), ARD_A4 (in), ARD_A5 (in), ARD_D0 (bidir), ARD_D1 (bidir), ARD_D2 (bidir), ARD_D3 (bidir), ARD_D4 (bidir), ARD_D5 (bidir), ARD_D6 (bidir), ARD_D7 (bidir), ARD_D8 (bidir), ARD_D9 (bidir), ARD_D10 (bidir), ARD_D11 (bidir), ARD_D12 (bidir), ARD_D13 (bidir), ARD_D14 (bidir), ARD_D15 (bidir), CODEC (harness SAI), DCMI_CLK (out), DCMI_D[0..7] (in), DCMI_HSYNC (in), DCMI_PIXCK (in), DCMI_VSYNC (in), DF_CKOUT (out), DFDATIN1 (in), DFDATIN3 (in), DFSDM (harness DFSDM), DSI_BL_CTRL (out), DSI_LANES (harness DSI_LANES), DSI_SPI (harness DSI_SPI), DSI_SWIRE (out), DSI_TE (in), DSI_USART (harness DSI_USART), HSE_STLINK (in), JOY_SEL (in), LED_GREEN (out), MFX_I2C (harness I2C), MFX_IRQ_OUT (in), MFX_WAKEUP (out), MIC_VDD (out), OCTOSPI Flash (harness OCTOSPI), PSRAM (harness PSRAM), RESET, SD (harness SD), STMOD+_ADC (in), STMOD+_I2C (harness I2C), STMOD+_INT (in), STMOD+_MISOs (in), STMOD+_MOSIs (out), STMOD+_PWM (out), STMOD+_RESET (out), STMOD+_SPI (harness SPI), STMOD+_UART (harness UART), SWCLK (in), SWDIO (bidir), SWO (out), USART_RX (in), USART_TX (out), USB_OTG (harness USB_OTG)

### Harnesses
OCTOSPI: OCTOSPIM_P2_IO1, OCTOSPIM_P2_IO0, OCTOSPIM_P2_CLK, OCTOSPIM_P2_CS, OCTOSPIM_P2_IO2, OCTOSPIM_P2_IO3, OCTOSPIM_P2_IO4, OCTOSPIM_P2_IO5, OCTOSPIM_P2_IO6, OCTOSPIM_P2_IO7, OCTOSPIM_P2_DQS
PSRAM: PSRAM_A[0..20], PSRAM_NE1, PSRAM_NBL0, PSRAM_WE, PSRAM_OE, PSRAM_D[0..15], PSRAM_NBL1, PSRAM_WAIT, PSRAM_CLK, PSRAM_ADV
DSI_USART: DSI_USART_CK, DSI_USART_TX
SAI: SAI_SDB, SAI_FSA, SAI_MCKA, SAI_SDA, SAI_SCKA
DFSDM: DATIN1, CKOUT
SD: uSD_D0, uSD_CLK, uSD_D1, uSD_D2, uSD_D3, uSD_CMD
USB_OTG: VBUS, DM, DP, ID
I2C: SDA, SCL
SPI: MISO, MOSI, CLK, CS
UART: RX, TX, RTS, CTS
DSI_SPI: DSI_SPI_CS, DSI_SPI_MOSI, DSI_SPI_CK, DSI_SPI_DCX
DSI_LANES: DSI_CK_P, DSI_CK_N, DSI_D0_P, DSI_D0_N, DSI_D1_N, DSI_D1_P

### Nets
+3V3: JP3.1
GND: C6.1 C7.2 C8.1 C9.1 C10.2 C11.1 C12.2 C13.2 C15.2 C17.2 C18.2 C20.2 C21.2 C23.2 C24.2 C25.1 C26.2 C27.2 C28.2 C50.2 C51.2 C61.2 C72.2 C85.2 C87.1 H1.1 H2.1 H3.1 H4.1 R15.1 U7.A7(VSS_1/IO_2) U7.B3(VSS_3/13) U7.C2(VSS_10) U7.C12(VSS_2) U7.F2(VSS_5) U7.F13(VSSIO_1) U7.H2(VSS_4/6) U7.H12(VSS_8/9_0/11) U7.J13(DSI_VSS_0) U7.K2(VSSA/VREF-) U7.K13(DSI_VSS_1) U7.M3(VSS_9) U7.M7(VSS_7) U7.M11(VSS_12) X2.2 X2.4
VDD: R16.1 R99.1 R100.1
VDD_MCU: C6.2 C12.1 C17.1 C18.1 C20.1 C21.1 C23.1 C24.1 C26.1 C27.1 C28.1 C61.1 C72.1 JP3.3 R61.2 U7.A3(VDD_3/13) U7.A8(VDD_9) U7.B6(VDDIO_2) U7.C1(VDD_12) U7.C13(VDD_2) U7.F12(VDDIO_1) U7.G2(VDD_5) U7.H13(VDD_8/11) U7.M13(VDD_REGDSI) U7.N3(VDD_4) U7.N7(VDD_6/7) U7.N11(VDD_1/9_0/10)
VDDA: C7.1 C8.2 L3.2 R14.2 U7.L2(VDDA)
VREF+: C13.1 C15.1 R14.1 U7.L1(VREF+)
ARD_A0: U7.M4(PA7) ; port ARD_A0
ARD_A1: U7.K4(PC4) ; port ARD_A1
ARD_A2: U7.K1(PC3) ; port ARD_A2
ARD_A3: U7.N4(PB0) ; port ARD_A3, port DSI_USART.DSI_USART_CK  [also labelled USART3_CK]
ARD_A4: U7.K3(PA0-WKUP) ; port ARD_A4
ARD_A5: U7.L3(PA5) ; port ARD_A5, port STMOD+_PWM  [also labelled STMOD+_PWM]
ARD_D0: U7.J2(PC0) ; port ARD_D0
ARD_D1: U7.J3(PC1) ; port ARD_D1
ARD_D2: U7.E6(PG11) ; port ARD_D2
ARD_D3: U7.H4(PF10) ; port ARD_D3
ARD_D4: U7.G12(PG6) ; port ARD_D4
ARD_D5: U7.M1(PA1) ; port ARD_D5
ARD_D6: U7.A5(PB4) ; port ARD_D6
ARD_D7: U7.N2(PA4) ; port ARD_D7, port DCMI_HSYNC, port STMOD+_ADC  [also labelled DCMI_HSYNC, STMOD+_ADC]
ARD_D8: U7.B12(PH15) ; port ARD_D8
ARD_D9: U7.C9(PH13) ; port ARD_D9
ARD_D10: U7.A12(PI0) ; port ARD_D10
ARD_D11: U7.L10(PB15) ; port ARD_D11, port STMOD+_SPI.MOSI, port DSI_SPI.DSI_SPI_MOSI  [also labelled SPI2_MOSI]
ARD_D12: U7.M12(PB14) ; port ARD_D12, port STMOD+_SPI.MISO, port DSI_SPI.DSI_SPI_DCX  [also labelled DSI_SPI_DCX, SPI2_MISO]
ARD_D13: U7.N13(PB13) ; port ARD_D13, port STMOD+_SPI.CLK, port DSI_SPI.DSI_SPI_CK  [also labelled SPI2_CLK]
ARD_D14: U7.F10(PG8) ; port ARD_D14, port STMOD+_I2C.SDA  [also labelled I2C3_SDA]
ARD_D15: U7.G10(PG7) ; port ARD_D15, port STMOD+_I2C.SCL  [also labelled I2C3_SCL]
BOOT0: R15.2 R16.2 U7.E5(PH3-BOOT0)
D0: U7.H11(PD14)
D1: U7.H10(PD15)
D2: U7.B8(PD0)
D3: U7.C8(PD1)
D4: U7.L7(PE7)
D5: U7.K6(PE8)
D6: U7.J6(PE9)
D7: U7.H6(PE10)
D8: U7.N8(PE11)
D9: U7.M8(PE12)
D10: U7.L8(PE13)
D11: U7.K7(PE14)
D12: U7.J7(PE15)
D13: U7.K10(PD8)
D14: U7.K9(PD9)
D15: U7.J10(PD10)
DCMI_CLK: U7.E11(PA8) ; port DCMI_CLK, port DSI_SWIRE  [also labelled DSI_SWIRE]
DCMI_D0: U7.F11(PC6) ; port STMOD+_INT  [also labelled STMOD+_INT]
DCMI_D1: U7.G11(PC7) ; port DFDATIN3  [also labelled DFDATIN3]
DCMI_D2: U7.M10(PH11)
DCMI_D3: U7.B13(PH12)
DCMI_D4: U7.D1(PE4)  [also labelled PSRAM_A20]
DCMI_D5: U7.D10(PI4)
DCMI_D6: U7.C4(PB8)
DCMI_D7: U7.B2(PI7) ; port STMOD+_RESET  [also labelled STMOD+_RESET]
DCMI_PIXCLK: U7.L9(PH5) ; port DCMI_PIXCK
DCMI_VSYNC: U7.E10(PI5) ; port DCMI_VSYNC
DF_CKOUT: U7.J4(PC2) ; port DF_CKOUT, port DFSDM.CKOUT  [project net CKOUT]
DFDATIN1: U7.N12(PB12) ; port DFDATIN1, port DFSDM.DATIN1  [project net DATIN1]
DSI_BL_CTRL: U7.L5(PB1) ; port DSI_BL_CTRL
DSI_CK_N: U7.K12(DSI_CK_N) ; port DSI_LANES.DSI_CK_N
DSI_CK_P: U7.K11(DSI_CK_P) ; port DSI_LANES.DSI_CK_P
DSI_D0_N: U7.L12(DSI_D0_N) ; port DSI_LANES.DSI_D0_N
DSI_D0_P: U7.L11(DSI_D0_P) ; port DSI_LANES.DSI_D0_P
DSI_D1_N: U7.J12(DSI_D1_N) ; port DSI_LANES.DSI_D1_N
DSI_D1_P: U7.J11(DSI_D1_P) ; port DSI_LANES.DSI_D1_P
DSI_SPI_USART_CS: U7.A13(PH14) ; port DSI_SPI.DSI_SPI_CS
DSI_TE: U7.M5(PF11) ; port DSI_TE
I2C1_SCL: R99.2 U7.C5(PB6) ; port MFX_I2C.SCL  [project net DCMI_I2C1_SCL]
I2C1_SDA: R100.2 U7.G6(PG13) ; port MFX_I2C.SDA  [project net DCMI_I2C1_SDA]
JOY_SEL: U7.E1(PC13-WKUP) ; port JOY_SEL
LED_GREEN: U7.K8(PH4) ; port LED_GREEN
MCO: SB28.2 ; port HSE_STLINK
MFX_IRQ_OUT: U7.B11(PI1) ; port MFX_IRQ_OUT
MFX_WAKEUP: U7.N5(PB2) ; port MFX_WAKEUP
MIC_VDD: U7.A2(PH2) ; port MIC_VDD
NRST: C10.1 U7.H3(NRST) ; port RESET  [project net DCMI_NRST]
OCTOSPIM_P2_CLK: U7.B9(PI6) ; port OCTOSPI Flash.OCTOSPIM_P2_CLK
OCTOSPIM_P2_CS: U7.F6(PG12) ; port OCTOSPI Flash.OCTOSPIM_P2_CS
OCTOSPIM_P2_DQS: U7.C6(PG15) ; port OCTOSPI Flash.OCTOSPIM_P2_DQS
OCTOSPIM_P2_IO0: U7.C3(PI11) ; port OCTOSPI Flash.OCTOSPIM_P2_IO0
OCTOSPIM_P2_IO1: U7.A1(PI10) ; port OCTOSPI Flash.OCTOSPIM_P2_IO1
OCTOSPIM_P2_IO2: U7.B1(PI9) ; port OCTOSPI Flash.OCTOSPIM_P2_IO2
OCTOSPIM_P2_IO3: U7.N10(PH8) ; port OCTOSPI Flash.OCTOSPIM_P2_IO3
OCTOSPIM_P2_IO4: U7.C11(PH9) ; port OCTOSPI Flash.OCTOSPIM_P2_IO4
OCTOSPIM_P2_IO5: U7.M9(PH10) ; port OCTOSPI Flash.OCTOSPIM_P2_IO5
OCTOSPIM_P2_IO6: U7.B7(PG9) ; port OCTOSPI Flash.OCTOSPIM_P2_IO6
OCTOSPIM_P2_IO7: U7.D6(PG10) ; port OCTOSPI Flash.OCTOSPIM_P2_IO7
OSC32_IN: C9.2 U7.F1(PC14-OSC32_IN) X1.1
OSC32_OUT: C11.2 U7.G1(PC15-OSC32_OUT) X1.2
OSC_IN_PH0: R54.2 SB28.1 U7.H1(PH0-OSC_IN)
OSC_OUT_PH1: R56.2 U7.J1(PH1-OSC_OUT)
PSRAM_A0: U7.F5(PF0)
PSRAM_A1: U7.F4(PF1)
PSRAM_A2: U7.F3(PF2)
PSRAM_A3: U7.G3(PF3)
PSRAM_A4: U7.G4(PF4)
PSRAM_A5: U7.G5(PF5)
PSRAM_A6: U7.N6(PF12)
PSRAM_A7: U7.M6(PF13)
PSRAM_A8: U7.L6(PF14)
PSRAM_A9: U7.K5(PF15)
PSRAM_A10: U7.J5(PG0)
PSRAM_A11: U7.H5(PG1)
PSRAM_A12: U7.H9(PG2)
PSRAM_A13: U7.G8(PG3)
PSRAM_A14: U7.G7(PG4)
PSRAM_A15: U7.G9(PG5)
PSRAM_A16: U7.J9(PD11)
PSRAM_A17: U7.J8(PD12)
PSRAM_A18: U7.H8(PD13)
PSRAM_A19: U7.D2(PE3)
PSRAM_ADV: U7.D5(PB7) ; port PSRAM.PSRAM_ADV
PSRAM_CLK: U7.E8(PD3) ; port PSRAM.PSRAM_CLK
PSRAM_NBL0: U7.A4(PE0) ; port PSRAM.PSRAM_NBL0
PSRAM_NBL1: U7.B4(PE1) ; port PSRAM.PSRAM_NBL1
PSRAM_NE1: U7.F7(PD7) ; port PSRAM.PSRAM_NE1
PSRAM_OE: U7.C7(PD4) ; port PSRAM.PSRAM_OE
PSRAM_WAIT: U7.E7(PD6) ; port PSRAM.PSRAM_WAIT
PSRAM_WE: U7.D7(PD5) ; port PSRAM.PSRAM_WE
SAI1_FSA: U7.D4(PB9) ; port CODEC.SAI_FSA
SAI1_MCKA: U7.D3(PE2) ; port CODEC.SAI_MCKA
SAI1_SCKA: U7.E4(PE5) ; port CODEC.SAI_SCKA
SAI1_SDA: U7.E3(PE6-WKUP) ; port CODEC.SAI_SDA
SAI1_SDB: U7.B5(PB5) ; port CODEC.SAI_SDB
SPI2_MISOs: U7.B10(PI2) ; port STMOD+_MISOs
SPI2_MOSIs: U7.C10(PI3) ; port STMOD+_MOSIs
SWCLK: U7.A10(PA14) ; port SWCLK
SWDIO: U7.A11(PA13) ; port SWDIO
SWO: U7.A6(PB3) ; port SWO
USART2_RX: U7.M2(PA3) ; port USART_RX
USART2_TX: U7.N1(PA2-WKUP) ; port USART_TX
USART3_CTS_SPI2_CS: U7.L4(PA6) ; port STMOD+_SPI.CS, port STMOD+_UART.CTS  [project net PMOD#1]
USART3_RTS: U7.A9(PA15) ; port STMOD+_UART.RTS
USART3_RX: U7.H7(PB11) ; port STMOD+_UART.RX
USART3_TX: U7.N9(PB10) ; port DSI_USART.DSI_USART_TX, port STMOD+_UART.TX
USB_OTGFS_DM: U7.E13(PA11) ; port USB_OTG.DM  [project net D_N]
USB_OTGFS_DP: U7.D13(PA12) ; port USB_OTG.DP  [project net D_P]
USB_OTGFS_ID: U7.D11(PA10) ; port USB_OTG.ID
USB_OTGFS_VBUS: U7.E12(PA9) ; port USB_OTG.VBUS
uSD_CLK: U7.F8(PC12) ; port SD.uSD_CLK
uSD_CMD: U7.D8(PD2) ; port SD.uSD_CMD
uSD_D0: U7.F9(PC8) ; port SD.uSD_D0
uSD_D1: U7.G13(PC9) ; port SD.uSD_D1
uSD_D2: U7.D9(PC10) ; port SD.uSD_D2
uSD_D3: U7.E9(PC11) ; port SD.uSD_D3
NetC25_2: C25.2 U7.L13(DSI_VCAP_0)
NetC50_1: C50.1 R54.1 X2.3
NetC51_1: C51.1 R56.1 X2.1
NetC85_1: C85.1 C87.2 JP3.2 L3.1 U7.D12(VDDUSB)
NetR61_1: R61.1 U7.E2(VBAT)

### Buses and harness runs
bus D[0..15]
bus DCMI_D[0..7] = port DCMI_D[0..7]
bus PSRAM_A[0..20]

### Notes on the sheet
- OCTO SPI Flash
- MFX
- Arduino
- PSRAM
- DSI LCD
- Camera
- ST_LINK
- CODEC&DFSDM
- STMOD+
- SD
- JOYSTICK
- USB_OTG

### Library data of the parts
C6 C8 C87 = Cap_22µF_X5R_16V_10%_1206: as C46 on sheet Camera
C7 C10 C12 C15 C17 C18 C20 C21 C23 C24 C26-C28 C61 C72 C85 = Cap: as C3 on sheet Camera
C9 C11 = Cap: Capacitor,5.6pF,0.25P,50V,NPO,0603; Manuf_1: YAGEO; Ordered by: Subcon
C13 = Cap Pol1: Tan Capacitor,1uF,10%,16V,Tan-A,TAJA105K016R; Manuf_1: AVX; Ordered by: Subcon; ECCN_US/EU: NA
C25 = Cap_2.2uF_X5R_10%_0603: Capacitor,2.2uF,16V,X5R,10%,0603,YAGEO; Manuf_Part_1: CC0603KRX5R7BB225; Ordered_By: Subcon; Fitted: YES
C50 C51 = Cap: Capacitor,6.8pF,0.25P,50V,NPO,0603; Manuf_1: YAGEO; Manuf_Part_1: CC0603CRNPO9BN6R8; Ordered by: Subcon
JP3 = Jumper3: Manuf_1: lyconn; Manuf_Part_1: 313103S111116; Ordered by: Subcon; ECCN_US/EU: NA
L3 = Inductor: as L1 on sheet LCD
R14 = res1: Resistor, 0 ,0603,1%,YAGEO; Manuf_Part_1: RC0603JR-070RL; Value: 0; Ordered by: Subcon; ECCN_US/EU: NA
R15 = res1: as R49 on sheet IDD_measurement
R16 = res1: Resistor,100K,0603,1%,YAGEO; Manuf_Part_1: RC0603FR-07100KL; Ordered by: Subcon; ECCN_US/EU: NA
R54 R56 = Res1: Resistor; Value: 1K
R61 = res1: as R79 on sheet IDD_measurement
R99 R100 = res1: Resistor,1.5K,0603,1%,YAGEO; Ordered by: Subcon; ECCN_US/EU: NA
SB28 = SB_OFF: Solder: NO
U7 = STM32L4R9AII6U: Ordered by: STM; Ref St: TBD
X1 = CRYSTAL_32K: 32.768kHz Crystal; Ordered by: STM; ECCN_US/EU: EAR99/NEC; Ref St: 9157034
